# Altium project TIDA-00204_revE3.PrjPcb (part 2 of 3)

## Sheet TIDA-00204_revE3_PHY_2.SchDoc: =DocumentName
size 431 x 279 mm; Date: Not shown in title block; ApprovedBy: Not shown in title block; CheckedBy: Not shown in title block; Author: Not shown in title block; CompanyName: Not shown in title block; DrawnBy: K. Mogensen; Engineer: K. Mogensen; Organization: Not shown in title block; Address1: Not shown in title block; Address2: Not shown in title block; Address3: Not shown in title block; Address4: Not shown in title block; DocumentNumber: 4; Revision: Use project parameter SCH_Rev; SheetNumber: 4; SheetTotal: 10; PageSetup: Record=PageOptions¦CenterHorizontal=True¦CenterVertical=True¦PrintScale=0.62¦XCorrection=1.00¦YCorrection=1.00¦PrintKind=0¦BorderSize=5000000¦LeftOffset=0¦BottomOffset=0¦Orientation=2¦PaperLength=1000¦PaperWidth=1000¦Scale=100¦PaperSource=15¦PrintQuality=600¦MediaType=1¦DitherType=10¦PrintScaleMode=1¦PaperKind=Letter
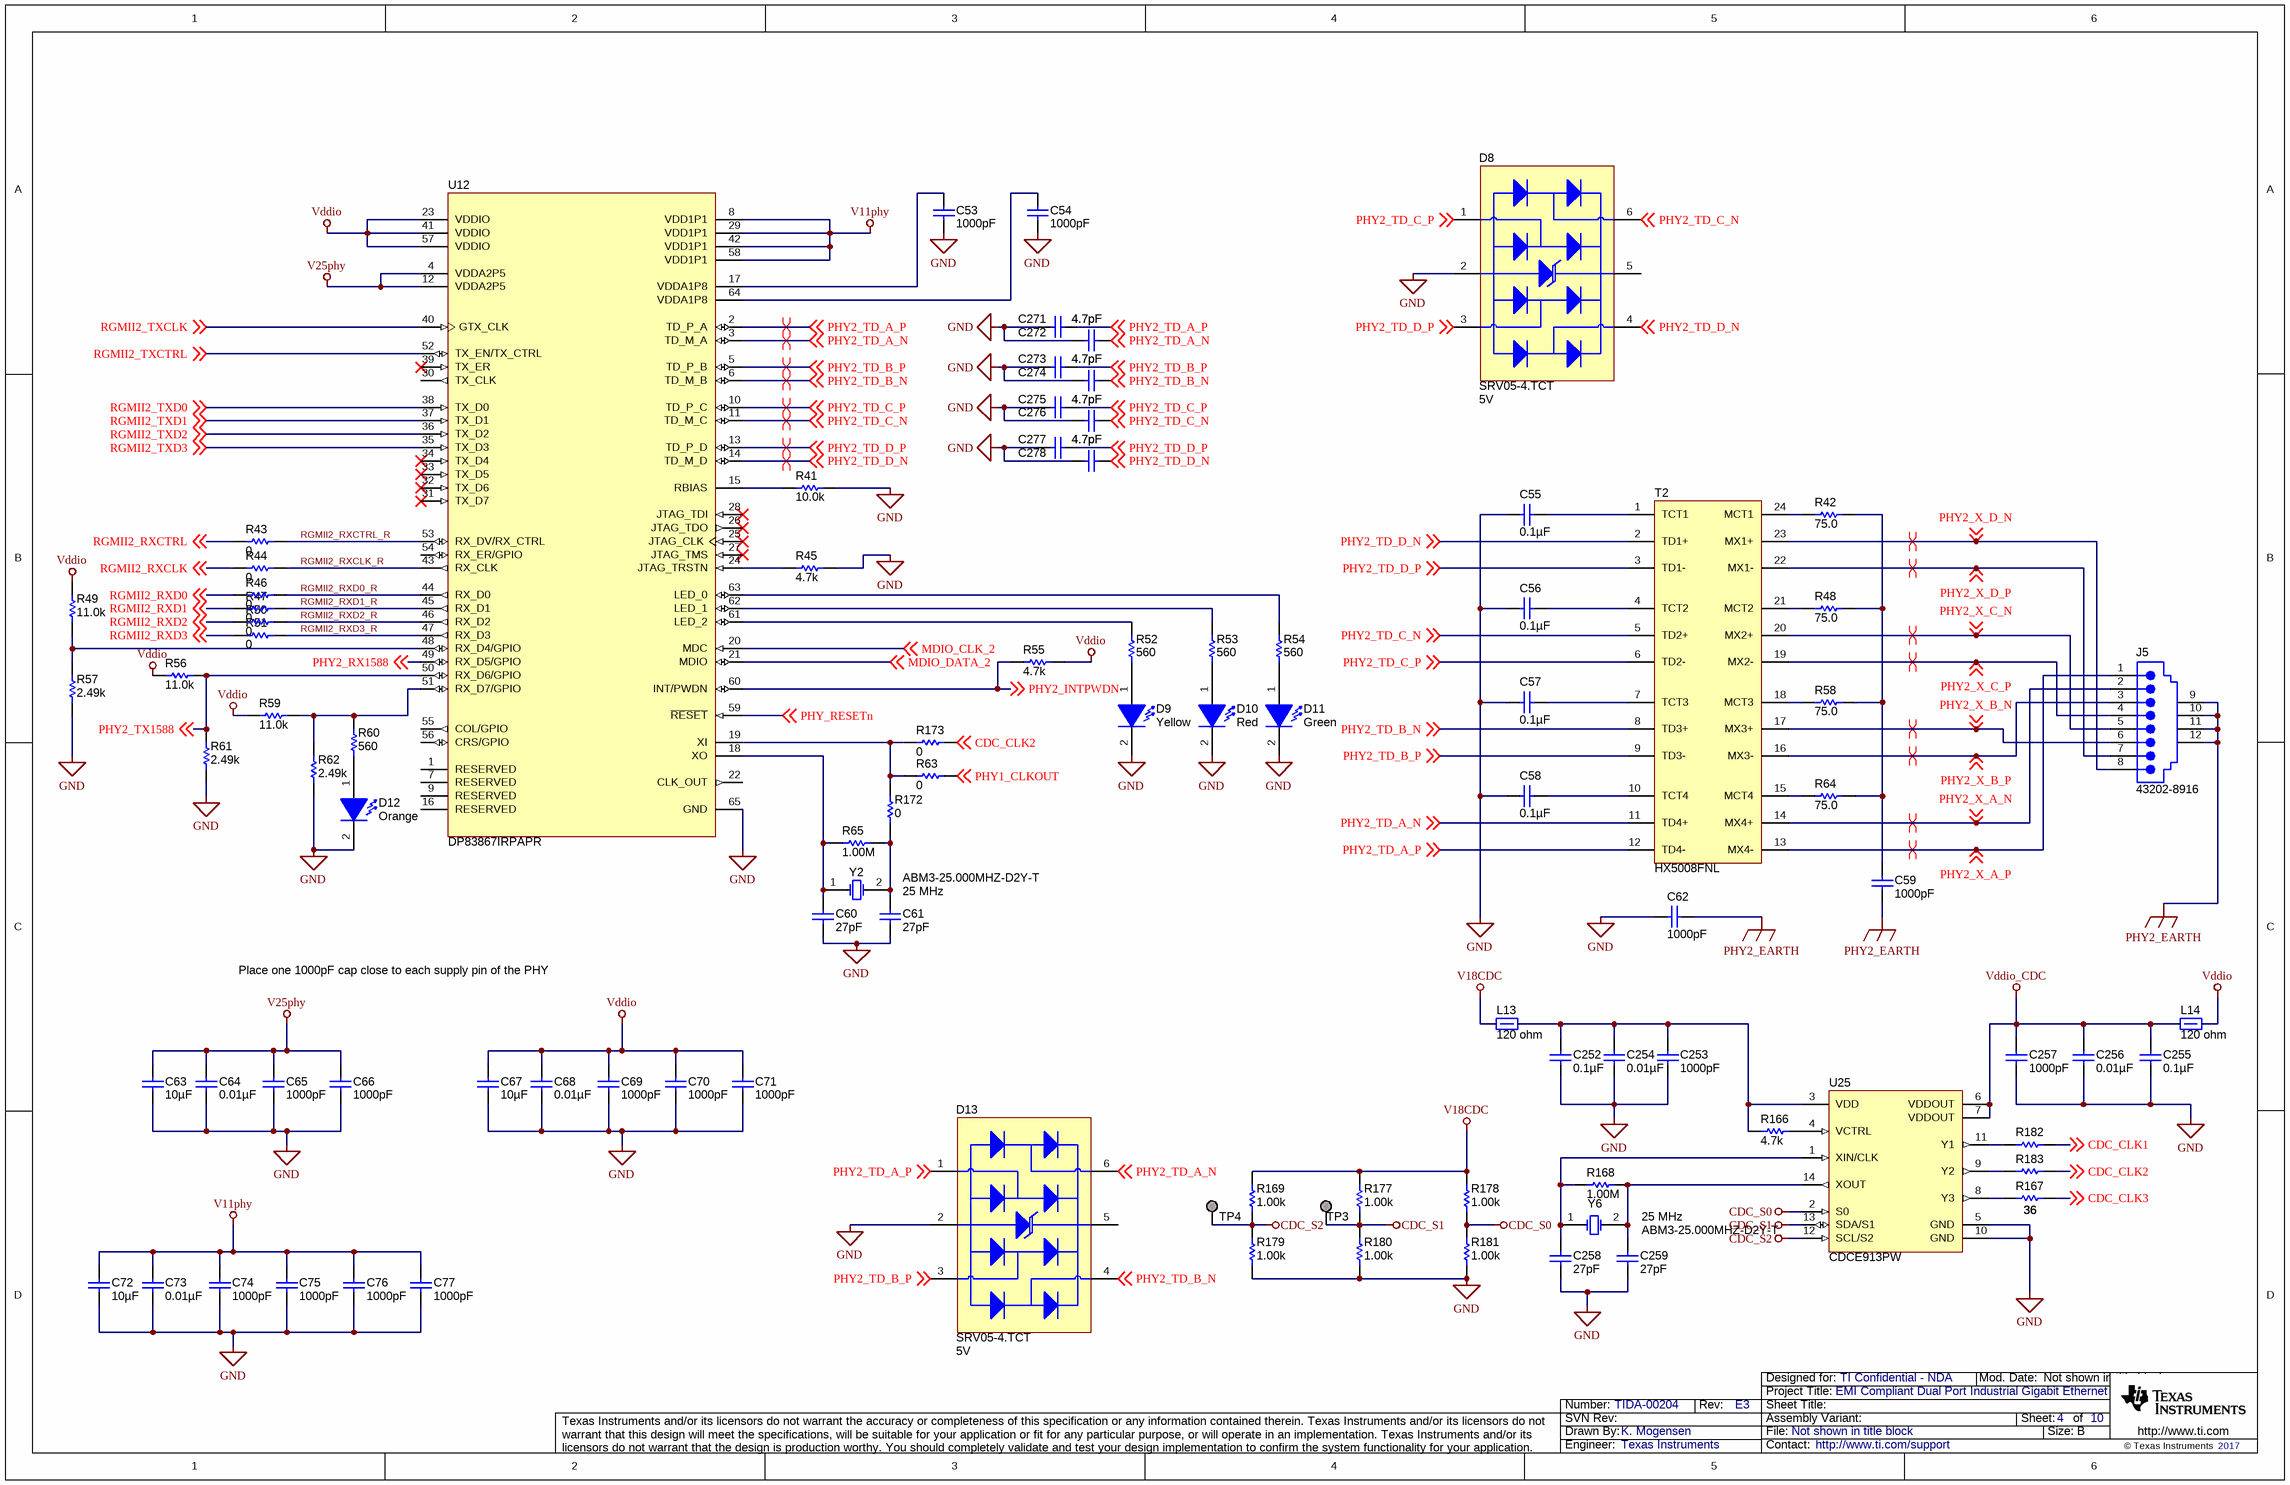
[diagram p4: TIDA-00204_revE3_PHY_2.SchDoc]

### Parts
C53  ValueDisplayed: 1000pF  [0201]  (hidden comment: GRM033R71C102KA01D)
C54  ValueDisplayed: 1000pF  [0201]  (hidden comment: GRM033R71C102KA01D)
C55  ValueDisplayed: 0.1µF  [0402]  (hidden comment: GRM155R71C104KA88D)
C56  ValueDisplayed: 0.1µF  [0402]  (hidden comment: GRM155R71C104KA88D)
C57  ValueDisplayed: 0.1µF  [0402]  (hidden comment: GRM155R71C104KA88D)
C58  ValueDisplayed: 0.1µF  [0402]  (hidden comment: GRM155R71C104KA88D)
C59  ValueDisplayed: 1000pF  [1206_190]  (hidden comment: 202R18W102KV4E)
C60  ValueDisplayed: 27pF  [0402]  (hidden comment: GRM1555C1H270JA01D)
C61  ValueDisplayed: 27pF  [0402]  (hidden comment: GRM1555C1H270JA01D)
C62  ValueDisplayed: 1000pF  [1812]  (hidden comment: 1812GC102KA1)
C63  ValueDisplayed: 10µF  [0603]  (hidden comment: C1608X5R1E106M080AC)
C64  ValueDisplayed: 0.01µF  [0201]  (hidden comment: GRM033R71A103KA01D)
C65  ValueDisplayed: 1000pF  [0201]  (hidden comment: GRM033R71C102KA01D)
C66  ValueDisplayed: 1000pF  [0201]  (hidden comment: GRM033R71C102KA01D)
C67  ValueDisplayed: 10µF  [0603]  (hidden comment: C1608X5R1E106M080AC)
C68  ValueDisplayed: 0.01µF  [0201]  (hidden comment: GRM033R71A103KA01D)
C69  ValueDisplayed: 1000pF  [0201]  (hidden comment: GRM033R71C102KA01D)
C70  ValueDisplayed: 1000pF  [0201]  (hidden comment: GRM033R71C102KA01D)
C71  ValueDisplayed: 1000pF  [0201]  (hidden comment: GRM033R71C102KA01D)
C72  ValueDisplayed: 10µF  [0603]  (hidden comment: C1608X5R1E106M080AC)
C73  ValueDisplayed: 0.01µF  [0201]  (hidden comment: GRM033R71A103KA01D)
C74  ValueDisplayed: 1000pF  [0201]  (hidden comment: GRM033R71C102KA01D)
C75  ValueDisplayed: 1000pF  [0201]  (hidden comment: GRM033R71C102KA01D)
C76  ValueDisplayed: 1000pF  [0201]  (hidden comment: GRM033R71C102KA01D)
C77  ValueDisplayed: 1000pF  [0201]  (hidden comment: GRM033R71C102KA01D)
C252  ValueDisplayed: 0.1µF  [0201]  (hidden comment: CL03A104KP3NNNC)
C253  ValueDisplayed: 1000pF  [0201]  (hidden comment: GRM033R71C102KA01D)
C254  ValueDisplayed: 0.01µF  [0201]  (hidden comment: GRM033R71A103KA01D)
C255  ValueDisplayed: 0.1µF  [0201]  (hidden comment: CL03A104KP3NNNC)
C256  ValueDisplayed: 0.01µF  [0201]  (hidden comment: GRM033R71A103KA01D)
C257  ValueDisplayed: 1000pF  [0201]  (hidden comment: GRM033R71C102KA01D)
C258  ValueDisplayed: 27pF  [0402]  (hidden comment: GRM1555C1H270JA01D)
C259  ValueDisplayed: 27pF  [0402]  (hidden comment: GRM1555C1H270JA01D)
C271  ValueDisplayed: 4.7pF  [0201]  (hidden comment: GRM0335C1H4R7CA01D)
C272  ValueDisplayed: 4.7pF  [0201]  (hidden comment: GRM0335C1H4R7CA01D)
C273  ValueDisplayed: 4.7pF  [0201]  (hidden comment: GRM0335C1H4R7CA01D)
C274  ValueDisplayed: 4.7pF  [0201]  (hidden comment: GRM0335C1H4R7CA01D)
C275  ValueDisplayed: 4.7pF  [0201]  (hidden comment: GRM0335C1H4R7CA01D)
C276  ValueDisplayed: 4.7pF  [0201]  (hidden comment: GRM0335C1H4R7CA01D)
C277  ValueDisplayed: 4.7pF  [0201]  (hidden comment: GRM0335C1H4R7CA01D)
C278  ValueDisplayed: 4.7pF  [0201]  (hidden comment: GRM0335C1H4R7CA01D)
D8  SRV05-4.TCT  value 5V  [SOT-23-6]
D9  value Yellow  [LY L29K_Yellow]  (hidden comment: LY L29K-J1K2-26-Z)
D10  value Red  [LS L29K_Red]  (hidden comment: LS L29K-G1J2-1-Z)
D11  value Green  [LG L29K_GREEN]  (hidden comment: LG L29K-G2J1-24-Z)
D12  value Orange  [LO L29K_Orange]  (hidden comment: LO L29K-J2L1-24-Z)
D13  SRV05-4.TCT  value 5V  [SOT-23-6]
J5  43202-8916  [Molex_43202-8916]
L13  value 120 ohm  [0402]  (hidden comment: MMZ1005Y121C)
L14  value 120 ohm  [0402]  (hidden comment: MMZ1005Y121C)
R41  ValueDisplayed: 10.0k  [0402]  (hidden comment: CRCW040210K0FKED)
R42  ValueDisplayed: 75.0  [0603]  (hidden comment: CRCW060375R0FKEA)
R43  ValueDisplayed: 0  [0402]  (hidden comment: CRCW04020000Z0ED)
R44  ValueDisplayed: 0  [0402]  (hidden comment: CRCW04020000Z0ED)
R45  ValueDisplayed: 4.7k  [0402]  (hidden comment: CRCW04024K70JNED)
R46  ValueDisplayed: 0  [0402]  (hidden comment: CRCW04020000Z0ED)
R47  ValueDisplayed: 0  [0402]  (hidden comment: CRCW04020000Z0ED)
R48  ValueDisplayed: 75.0  [0603]  (hidden comment: CRCW060375R0FKEA)
R49  ValueDisplayed: 11.0k  [0402]  (hidden comment: CRCW040211K0FKED)
R50  ValueDisplayed: 0  [0402]  (hidden comment: CRCW04020000Z0ED)
R51  ValueDisplayed: 0  [0402]  (hidden comment: CRCW04020000Z0ED)
R52  ValueDisplayed: 560  [0402]  (hidden comment: CRCW0402560RJNED)
R53  ValueDisplayed: 560  [0402]  (hidden comment: CRCW0402560RJNED)
R54  ValueDisplayed: 560  [0402]  (hidden comment: CRCW0402560RJNED)
R55  ValueDisplayed: 4.7k  [0402]  (hidden comment: CRCW04024K70JNED)
R56  ValueDisplayed: 11.0k  [0402]  (hidden comment: CRCW040211K0FKED)
R57  ValueDisplayed: 2.49k  [0402]  (hidden comment: CRCW04022K49FKED)
R58  ValueDisplayed: 75.0  [0603]  (hidden comment: CRCW060375R0FKEA)
R59  ValueDisplayed: 11.0k  [0402]  (hidden comment: CRCW040211K0FKED)
R60  ValueDisplayed: 560  [0402]  (hidden comment: CRCW0402560RJNED)
R61  ValueDisplayed: 2.49k  [0402]  (hidden comment: CRCW04022K49FKED)
R62  ValueDisplayed: 2.49k  [0402]  (hidden comment: CRCW04022K49FKED)
R63  ValueDisplayed: 0  [0402]  (hidden comment: CRCW04020000Z0ED)
R64  ValueDisplayed: 75.0  [0603]  (hidden comment: CRCW060375R0FKEA)
R65  ValueDisplayed: 1.00M  [0402]  (hidden comment: CRCW04021M00FKED)
R166  ValueDisplayed: 4.7k  [0402]  (hidden comment: CRCW04024K70JNED)
R167  ValueDisplayed: 36  [0402]  (hidden comment: CRCW040236R0JNED)
R168  ValueDisplayed: 1.00M  [0402]  (hidden comment: CRCW04021M00FKED)
R169  ValueDisplayed: 1.00k  [0402]  (hidden comment: CRCW04021K00FKED)
R172  ValueDisplayed: 0  [0402]  (hidden comment: CRCW04020000Z0ED)
R173  ValueDisplayed: 0  [0402]  (hidden comment: CRCW04020000Z0ED)
R177  ValueDisplayed: 1.00k  [0402]  (hidden comment: CRCW04021K00FKED)
R178  ValueDisplayed: 1.00k  [0402]  (hidden comment: CRCW04021K00FKED)
R179  ValueDisplayed: 1.00k  [0402]  (hidden comment: CRCW04021K00FKED)
R180  ValueDisplayed: 1.00k  [0402]  (hidden comment: CRCW04021K00FKED)
R181  ValueDisplayed: 1.00k  [0402]  (hidden comment: CRCW04021K00FKED)
R182  ValueDisplayed: 36  [0402]  (hidden comment: CRCW040236R0JNED)
R183  ValueDisplayed: 36  [0402]  (hidden comment: CRCW040236R0JNED)
T2  HX5008FNL  [PULSE_HX5008FNL]
TP3  TESTPOINT  [OXLEY_SMOX_060_B1_LP]  (value not drawn)  (no BOM)
TP4  TESTPOINT  [OXLEY_SMOX_060_B1_LP]  (value not drawn)  (no BOM)
U12  DP83867IRPAPR  [PAP0064M_N]
U25  CDCE913PW  [PW0014A_N]
Y2  ABM3-25.000MHZ-D2Y-T  Frequency: 25 MHz  [XTAL_ABM3]
Y6  ABM3-25.000MHZ-D2Y-T  Frequency: 25 MHz  [XTAL_ABM3]

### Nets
CDC_S0: R178.1 R181.2 U25.2(S0)
CDC_S1: R177.1 R180.2 TP3.1 U25.13(SDA/S1)
CDC_S2: R169.1 R179.2 TP4.1 U25.12(SCL/S2)
GND: C53.2 C54.2 C55.2 C56.2 C57.2 C58.2 C60.2 C61.2 C62.2 C63.2 C64.2 C65.2 C66.2 C67.2 C68.2 C69.2 C70.2 C71.2 C72.2 C73.2 C74.2 C75.2 C76.2 C77.2 C252.2 C253.2 C254.2 C255.2 C256.2 C257.2 C258.2 C259.2 C271.1 C272.1 C273.1 C274.1 C275.1 C276.1 C277.1 C278.1 D8.2 D9.2(K) D10.2(K) D11.2(K) D12.2(K) D13.2 R41.1 R45.1 R57.2 R61.1 R62.1 R179.1 R180.1 R181.1 U12.65(GND) U25.5(GND) U25.10(GND)
PHY2_EARTH: C59.2 C62.1 J5.9 J5.10 J5.11 J5.12
V11phy: C72.1 C73.1 C74.1 C75.1 C76.1 C77.1 U12.8(VDD1P1) U12.29(VDD1P1) U12.42(VDD1P1) U12.58(VDD1P1)
V18CDC: L13.1 R169.2 R177.2 R178.2
V25phy: C63.1 C64.1 C65.1 C66.1 U12.4(VDDA2P5) U12.12(VDDA2P5)
Vddio: C67.1 C68.1 C69.1 C70.1 C71.1 L14.1 R49.2 R55.1 R56.1 R59.2 U12.23(VDDIO) U12.41(VDDIO) U12.57(VDDIO)
Vddio_CDC: C255.1 C256.1 C257.1 L14.2 U25.6(VDDOUT) U25.7(VDDOUT)
CDC_CLK1: R182.2 ; off-sheet CDC_CLK1
CDC_CLK2: R173.2 R183.2 ; off-sheet CDC_CLK2
CDC_CLK3: R167.2 ; off-sheet CDC_CLK3
MDIO_CLK_2: U12.20(MDC) ; off-sheet MDIO_CLK_2
MDIO_DATA_2: U12.21(MDIO) ; off-sheet MDIO_DATA_2
PHY1_CLKOUT: R63.1 ; off-sheet PHY1_CLKOUT
PHY2_INTPWDN: R55.2 U12.60(INT/PWDN) ; off-sheet PHY2_INTPWDN
PHY2_RX1588: U12.49(RX_D5/GPIO) ; off-sheet PHY2_RX1588
PHY2_TD_A_N: C272.2 D13.6 T2.11(TD4+) U12.3(TD_M_A) ; off-sheet PHY2_TD_A_N
PHY2_TD_A_P: C271.2 D13.1 T2.12(TD4-) U12.2(TD_P_A) ; off-sheet PHY2_TD_A_P
PHY2_TD_B_N: C274.2 D13.4 T2.8(TD3+) U12.6(TD_M_B) ; off-sheet PHY2_TD_B_N
PHY2_TD_B_P: C273.2 D13.3 T2.9(TD3-) U12.5(TD_P_B) ; off-sheet PHY2_TD_B_P
PHY2_TD_C_N: C276.2 D8.6 T2.5(TD2+) U12.11(TD_M_C) ; off-sheet PHY2_TD_C_N
PHY2_TD_C_P: C275.2 D8.1 T2.6(TD2-) U12.10(TD_P_C) ; off-sheet PHY2_TD_C_P
PHY2_TD_D_N: C278.2 D8.4 T2.2(TD1+) U12.14(TD_M_D) ; off-sheet PHY2_TD_D_N
PHY2_TD_D_P: C277.2 D8.3 T2.3(TD1-) U12.13(TD_P_D) ; off-sheet PHY2_TD_D_P
PHY2_TX1588: R56.2 R61.2 U12.50(RX_D6/GPIO) ; off-sheet PHY2_TX1588
PHY2_X_A_N: J5.2 T2.14(MX4+) ; off-sheet PHY2_X_A_N
PHY2_X_A_P: J5.1 T2.13(MX4-) ; off-sheet PHY2_X_A_P
PHY2_X_B_N: J5.6 T2.17(MX3+) ; off-sheet PHY2_X_B_N
PHY2_X_B_P: J5.3 T2.16(MX3-) ; off-sheet PHY2_X_B_P
PHY2_X_C_N: J5.5 T2.20(MX2+) ; off-sheet PHY2_X_C_N
PHY2_X_C_P: J5.4 T2.19(MX2-) ; off-sheet PHY2_X_C_P
PHY2_X_D_N: J5.8 T2.23(MX1+) ; off-sheet PHY2_X_D_N
PHY2_X_D_P: J5.7 T2.22(MX1-) ; off-sheet PHY2_X_D_P
PHY_RESETn: U12.59(~{RESET}) ; off-sheet PHY_RESETn
RGMII2_RXCLK: R44.1 ; off-sheet RGMII2_RXCLK
RGMII2_RXCLK_R: R44.2 U12.43(RX_CLK)
RGMII2_RXCTRL: R43.1 ; off-sheet RGMII2_RXCTRL
RGMII2_RXCTRL_R: R43.2 U12.53(RX_DV/RX_CTRL)
RGMII2_RXD0: R46.1 ; off-sheet RGMII2_RXD0
RGMII2_RXD0_R: R46.2 U12.44(RX_D0)
RGMII2_RXD1: R47.1 ; off-sheet RGMII2_RXD1
RGMII2_RXD1_R: R47.2 U12.45(RX_D1)
RGMII2_RXD2: R50.1 ; off-sheet RGMII2_RXD2
RGMII2_RXD2_R: R50.2 U12.46(RX_D2)
RGMII2_RXD3: R51.1 ; off-sheet RGMII2_RXD3
RGMII2_RXD3_R: R51.2 U12.47(RX_D3)
RGMII2_TXCLK: U12.40(GTX_CLK) ; off-sheet RGMII2_TXCLK
RGMII2_TXCTRL: U12.52(TX_EN/TX_CTRL) ; off-sheet RGMII2_TXCTRL
RGMII2_TXD0: U12.38(TX_D0) ; off-sheet RGMII2_TXD0
RGMII2_TXD1: U12.37(TX_D1) ; off-sheet RGMII2_TXD1
RGMII2_TXD2: U12.36(TX_D2) ; off-sheet RGMII2_TXD2
RGMII2_TXD3: U12.35(TX_D3) ; off-sheet RGMII2_TXD3
NetC53_1: C53.1 U12.17(VDDA1P8)
NetC54_1: C54.1 U12.64(VDDA1P8)
NetC55_1: C55.1 T2.1(TCT1)
NetC56_1: C56.1 T2.4(TCT2)
NetC57_1: C57.1 T2.7(TCT3)
NetC58_1: C58.1 T2.10(TCT4)
NetC59_1: C59.1 R42.2 R48.2 R58.2 R64.2
NetC60_1: C60.1 R65.1 U12.18(XO) Y2.1(OSC1)
NetC61_1: C61.1 R65.2 R172.1 Y2.2(OSC2)
NetC252_1: C252.1 C253.1 C254.1 L13.2 R166.1 U25.3(VDD)
NetC258_1: C258.1 R168.1 U25.1(XIN/CLK) Y6.1(OSC1)
NetC259_1: C259.1 R168.2 U25.14(XOUT) Y6.2(OSC2)
NetD9_1: D9.1(A) R52.1
NetD10_1: D10.1(A) R53.1
NetD11_1: D11.1(A) R54.1
NetD12_1: D12.1(A) R60.2
NetR41_2: R41.2 U12.15(RBIAS)
NetR42_1: R42.1 T2.24(MCT1)
NetR45_2: R45.2 U12.24(JTAG_TRSTN)
NetR48_1: R48.1 T2.21(MCT2)
NetR49_1: R49.1 R57.1 U12.48(RX_D4/GPIO)
NetR52_2: R52.2 U12.61(LED_2)
NetR53_2: R53.2 U12.62(LED_1)
NetR54_2: R54.2 U12.63(LED_0)
NetR58_1: R58.1 T2.18(MCT3)
NetR59_1: R59.1 R60.1 R62.2 U12.51(RX_D7/GPIO)
NetR63_2: R63.2 R172.2 R173.1 U12.19(XI)
NetR64_1: R64.1 T2.15(MCT4)
NetR166_2: R166.2 U25.4(VCTRL)
NetR167_1: R167.1 U25.8(Y3)
NetR182_1: R182.1 U25.11(Y1)
NetR183_1: R183.1 U25.9(Y2)

Not connected (* = marked no-connect by the designer): D8 5; D13 5; U12 1(RESERVED) 7(RESERVED) 9(RESERVED) 16(RESERVED) 22(CLK_OUT) 25(JTAG_CLK)* 26(JTAG_TDO)* 27(JTAG_TMS)* 28(JTAG_TDI)* 30(TX_CLK) 31(TX_D7)* 32(TX_D6)* 33(TX_D5)* 34(TX_D4)* 39(TX_ER)* 54(RX_ER/GPIO) 55(COL/GPIO) 56(CRS/GPIO)

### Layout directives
differential pair: PHY2_TD_A_N, PHY2_TD_A_P, PHY2_TD_B_N, PHY2_TD_B_P, PHY2_TD_C_N, PHY2_TD_C_P, PHY2_TD_D_N, PHY2_TD_D_P, PHY2_X_A_N, PHY2_X_A_P, PHY2_X_B_N, PHY2_X_B_P, PHY2_X_C_N, PHY2_X_C_P, PHY2_X_D_N, PHY2_X_D_P

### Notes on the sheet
- Place one 1000pF cap close to each supply pin of the PHY

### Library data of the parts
C53 C54 C65 C66 C69-C71 C74-C77 C253 C257 = GRM033R71C102KA01D: CAP, CERM, 1000 pF, 16 V, +/- 10%, X7R, 0201; Manufacturer: MuRata; Polarized: N; CompType: Capacitor; Value: 1000pF; U/M: EA; Cap_F: 0.000000001; Tolerance_%: 10; Value1: Unknown; VDC_V: 16; Value2: 16V; TaMin_C: -55; TaMax_C: 125
C55-C58 = GRM155R71C104KA88D: CAP, CERM, 0.1 µF, 16 V, +/- 10%, X7R, 0402; Manufacturer: MuRata; Polarized: N; CompType: Capacitor; Value: 0.1uF; U/M: EA; Cap_F: 0.0000001; Tolerance_%: 10; Value1: Unknown; VDC_V: 16; Value2: 16V; TaMin_C: -55; TaMax_C: 125
C59 = 202R18W102KV4E: CAP, CERM, 1000 pF, 2000 V, +/- 10%, X7R, 1206_190; Manufacturer: Johanson Technology; Polarized: N; CompType: Capacitor; Value: 1000pF; U/M: EA; Cap_F: 0.000000001; Tolerance_%: 10; Value1: Unknown; VDC_V: 2000; Value2: 2000V; TaMin_C: -55; TaMax_C: 125
C60 C61 C258 C259 = GRM1555C1H270JA01D: CAP, CERM, 27 pF, 50 V, +/- 5%, C0G/NP0, 0402; Manufacturer: MuRata; Polarized: N; CompType: Capacitor; Value: 27pF; U/M: EA; Cap_F: 0.000000000027; Tolerance_%: 5; Value1: Unknown; VDC_V: 50; Value2: 50V; TaMin_C: -55; TaMax_C: 125
C62 = 1812GC102KA1: CAP, CERM, 1000 pF, 2000 V, +/- 10%, X7R, 1812; Manufacturer: AVX; Polarized: N; CompType: Capacitor; Value: 1000pF; U/M: EA; Cap_F: 0.000000001; Tolerance_%: 10; Value1: Unknown; VDC_V: 2000; Value2: 2000V; TaMin_C: -55; TaMax_C: 125
C63 C67 C72 = C1608X5R1E106M080AC: CAP, CERM, 10 µF, 25 V, +/- 20%, X5R, 0603; Manufacturer: TDK; Polarized: N; CompType: Capacitor; Value: 10uF; U/M: EA; Cap_F: 0.00001; Tolerance_%: 20; Value1: Unknown; VDC_V: 25; Value2: 25V; TaMin_C: -55; TaMax_C: 85
C64 C68 C73 C254 C256 = GRM033R71A103KA01D: CAP, CERM, 0.01 µF, 10 V, +/- 10%, X7R, 0201; Manufacturer: MuRata; Polarized: N; CompType: Capacitor; Value: 0.01uF; U/M: EA; Cap_F: 0.00000001; Tolerance_%: 10; Value1: Unknown; Value2: 10V; TaMin_C: -55; TaMax_C: 125
C252 C255 = CL03A104KP3NNNC: CAP, CERM, 0.1 µF, 10 V, +/- 10%, X5R, 0201; Manufacturer: Samsung; Polarized: N; CompType: Capacitor; Value: 0.1uF; U/M: EA; Cap_F: 0.0000001; Tolerance_%: 10; Value1: Unknown; Value2: 10V; TaMin_C: -55; TaMax_C: 85
C271-C278 = GRM0335C1H4R7CA01D: CAP, CERM, 4.7 pF, 50 V, +/- 5%, C0G/NP0, 0201; Manufacturer: MuRata; Polarized: N; CompType: Capacitor; Value: 4.7pF; U/M: EA; Cap_F: 0.0000000000047; Tolerance_%: 5; Value1: Unknown; VDC_V: 50; Value2: 50V; TaMin_C: -55; TaMax_C: 125
D8 D13 = SRV05-4.TCT: Diode, TVS, Bi, 5 V, 300 W, SOT-23-6; Manufacturer: Semtech; SymbolCreator: Altium; U/M: EA; Power_W: 300; Vr_V: 5; Value1: 300W
D9 = LY L29K-J1K2-26-Z: LED, Yellow, SMD; Manufacturer: OSRAM; Vf_V: 1.8; Value2: 1.8V; Io_A: 0.002; Tjmax_C: 110; Value1: W; U/M: EA
D10 = LS L29K-G1J2-1-Z: LED, Red, SMD; Manufacturer: OSRAM; Vf_V: 1.8; Value2: 1.8V; Io_A: 0.02; Vr_V: 12; Tjmax_C: 110; Value1: W; Angle: 160; U/M: EA
D11 = LG L29K-G2J1-24-Z: LED, Green, SMD; Manufacturer: OSRAM; Vf_V: 1.7; Value2: 1.7V; Io_A: 0.002; Tjmax_C: 110; Value1: W; U/M: EA
D12 = LO L29K-J2L1-24-Z: LED, Orange, SMD; Manufacturer: OSRAM; Vf_V: 1.8; Value2: 1.8V; Io_A: 0.02; Vr_V: 12; Tjmax_C: 110; Value1: W; Angle: 160; U/M: EA
J5 = 43202-8916: Modular Jack(Shielded), Gold, R/A, TH; Manufacturer: Molex; SymbolCreator: Altium; U/M: EA
L13 L14 = MMZ1005Y121C: Ferrite Bead, 120 ohm @ 100 MHz, 0.4 A, 0402; Manufacturer: TDK; Imax_A: 0.4; DCR_ohm: 0.18; Value1: 0.18 ohm; Value2: 0.4A; ZTyp@100MHz_Ohm: 120
R41 = CRCW040210K0FKED: RES, 10.0 k, 1%, 0.063 W, 0402; Manufacturer: Vishay-Dale; CompType: Resistor; Value: 10.0k; Res_ohm: 10000; Value_Code: 10k0; Tolerance_%: 1; Power_W: 0.063; Value2: 0.063W; VDC_V: 50; TempCo: 100 ppm/C; EIA_Code: E96; U/M: EA
R42 R48 R58 R64 = CRCW060375R0FKEA: RES, 75.0, 1%, 0.1 W, 0603; Manufacturer: Vishay-Dale; CompType: Resistor; Value: 75.0; Res_ohm: 75; Value_Code: 75R0; Tolerance_%: 1; Power_W: 0.1; Value2: 0.1W; TempCo: 100 ppm/C; EIA_Code: E96; U/M: EA
R43 R44 R46 R47 R50 R51 R63 R172 R173 = CRCW04020000Z0ED: RES, 0, 5%, 0.063 W, 0402; Manufacturer: Vishay-Dale; CompType: Resistor; Value: 0; Value_Code: 0000; Tolerance_%: 5; Power_W: 0.063; Value2: 0.063W; VDC_V: 50; TempCo: 200 ppm/C; EIA_Code: E24; U/M: EA
R45 R55 R166 = CRCW04024K70JNED: RES, 4.7 k, 5%, 0.063 W, 0402; Manufacturer: Vishay-Dale; CompType: Resistor; Value: 4.7k; Res_ohm: 4700; Value_Code: 4k70; Tolerance_%: 5; Power_W: 0.063; Value2: 0.063W; VDC_V: 50; TempCo: 200 ppm/C; EIA_Code: E24; U/M: EA
R49 R56 R59 = CRCW040211K0FKED: RES, 11.0 k, 1%, 0.063 W, 0402; Manufacturer: Vishay-Dale; CompType: Resistor; Value: 11.0k; Res_ohm: 11000; Value_Code: 11k0; Tolerance_%: 1; Power_W: 0.063; Value2: 0.063W; VDC_V: 50; TempCo: 100 ppm/C; EIA_Code: E96; U/M: EA
R52-R54 R60 = CRCW0402560RJNED: RES, 560, 5%, 0.063 W, 0402; Manufacturer: Vishay-Dale; CompType: Resistor; Value: 560; Value_Code: 560R; Tolerance_%: 5; Power_W: 0.063; Value2: 0.063W; VDC_V: 50; TempCo: 200 ppm/C; EIA_Code: E24; U/M: EA
R57 R61 R62 = CRCW04022K49FKED: RES, 2.49 k, 1%, 0.063 W, 0402; Manufacturer: Vishay-Dale; CompType: Resistor; Value: 2.49k; Res_ohm: 2490; Value_Code: 2k49; Tolerance_%: 1; Power_W: 0.063; Value2: 0.063W; VDC_V: 50; TempCo: 100 ppm/C; EIA_Code: E96; U/M: EA
R65 R168 = CRCW04021M00FKED: RES, 1.00 M, 1%, 0.063 W, 0402; Manufacturer: Vishay-Dale; CompType: Resistor; Value: 1.00Meg; Res_ohm: 1000000; Value_Code: 1M00; Tolerance_%: 1; Power_W: 0.063; Value2: 0.063W; VDC_V: 50; TempCo: 100 ppm/C; EIA_Code: E96; U/M: EA
R167 R182 R183 = CRCW040236R0JNED: RES, 36, 5%, 0.063 W, 0402; Manufacturer: Vishay-Dale; CompType: Resistor; Value: 36; Value_Code: 36R0; Tolerance_%: 5; Power_W: 0.063; Value2: 0.063W; VDC_V: 50; TempCo: 200 ppm/C; EIA_Code: E24; U/M: EA
R169 R177-R181 = CRCW04021K00FKED: RES, 1.00 k, 1%, 0.063 W, 0402; Manufacturer: Vishay-Dale; CompType: Resistor; Value: 1.00k; Res_ohm: 1000; Value_Code: 1k00; Tolerance_%: 1; Power_W: 0.063; Value2: 0.063W; VDC_V: 50; TempCo: 100 ppm/C; EIA_Code: E96; U/M: EA
T2 = HX5008FNL: Transformer, 325 uH, SMT; Manufacturer: Pulse Engineering; SymbolCreator: Altium; Value: 325 uH; U/M: EA
TP3 TP4 = SMOX/060/B1LP.R3K: Test Point, Silver, SMD; Manufacturer: Oxley; U/M: EA
U12 = DP83867IRPAPR: Robust, Low Power 10/100/1000 Ethernet Physical Layer Transceiver, PAP0064M; Alternate PartNumber: DP83867IRPAPT; Manufacturer: Texas Instruments; SymbolCreator: Altium; CompType: IC; U/M: EA
U25 = CDCE913PW: Programmable 1-PLL VCXO Clock Synthesizer With 1.8-V, 2.5-V, and 3.3-V Outputs, PW0014A; Manufacturer: Texas Instruments; SymbolCreator: a0411947; CompType: IC; U/M: EA
Y2 Y6 = ABM3-25.000MHZ-D2Y-T: Crystal, 25 MHz, 18 pF, SMD; Manufacturer: Abracon Corportation; SymbolCreator: a0412235; U/M: EA; TaMin_C: -40; TaMax_C: 85; Frequency Stability: ±30ppm

## Sheet TIDA-00204_revE3_PS_0.SchDoc: =DocumentName
size 431 x 279 mm; Date: Not shown in title block; ApprovedBy: Not shown in title block; CheckedBy: Not shown in title block; Author: Not shown in title block; CompanyName: Not shown in title block; DrawnBy: K. Mogensen; Engineer: K. Mogensen; Organization: Not shown in title block; Address1: Not shown in title block; Address2: Not shown in title block; Address3: Not shown in title block; Address4: Not shown in title block; DocumentNumber: 1; Revision: Use project parameter SCH_Rev; SheetNumber: 1; SheetTotal: 10; PageSetup: Record=PageOptions¦CenterHorizontal=True¦CenterVertical=True¦PrintScale=0.62¦XCorrection=1.00¦YCorrection=1.00¦PrintKind=0¦BorderSize=5000000¦LeftOffset=0¦BottomOffset=0¦Orientation=2¦PaperLength=1000¦PaperWidth=1000¦Scale=100¦PaperSource=15¦PrintQuality=600¦MediaType=1¦DitherType=10¦PaperKind=Letter¦PrintScaleMode=1
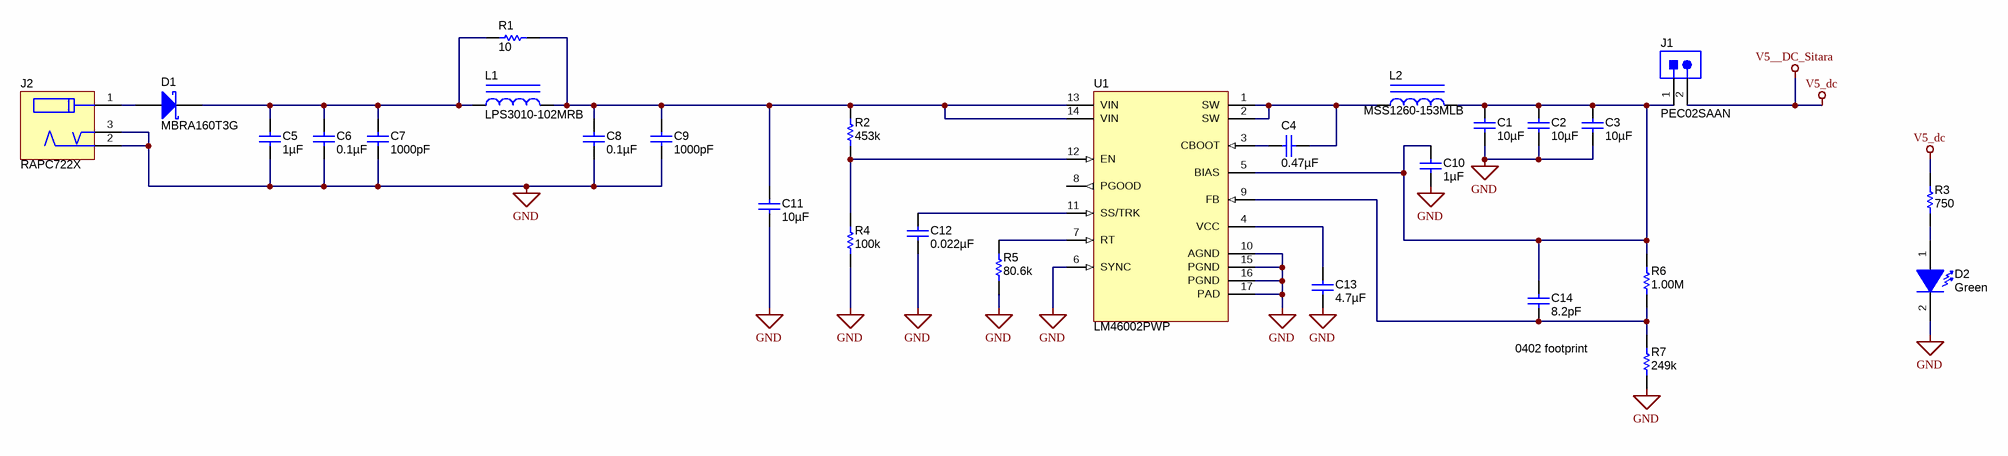
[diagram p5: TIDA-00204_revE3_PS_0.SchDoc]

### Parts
C1  ValueDisplayed: 10µF  [0603]  (hidden comment: C1608X5R1E106M080AC)
C2  ValueDisplayed: 10µF  [0603]  (hidden comment: C1608X5R1E106M080AC)
C3  ValueDisplayed: 10µF  [0603]  (hidden comment: C1608X5R1E106M080AC)
C4  ValueDisplayed: 0.47µF  [0805_HV]  (hidden comment: GRM21BR72A474KA73L)
C5  ValueDisplayed: 1µF  [0805_145]  (hidden comment: C2012X7S2A105K125AB)
C6  ValueDisplayed: 0.1µF  [0603]  (hidden comment: GRM188R72A104KA35D)
C7  ValueDisplayed: 1000pF  [0603]  (hidden comment: GRM188R72A102KA01D)
C8  ValueDisplayed: 0.1µF  [0603]  (hidden comment: GRM188R72A104KA35D)
C9  ValueDisplayed: 1000pF  [0603]  (hidden comment: GRM188R72A102KA01D)
C10  ValueDisplayed: 1µF  [0603]  (hidden comment: GRM188R71E105KA12D)
C11  ValueDisplayed: 10µF  [2220]  (hidden comment: C5750X7S2A106M)
C12  ValueDisplayed: 0.022µF  [0402]  (hidden comment: GRM155R71H223KA12D)
C13  ValueDisplayed: 4.7µF  [0603]  (hidden comment: GRM188R61C475KAAJ)
C14  ValueDisplayed: 8.2pF  [0402]  (hidden comment: GRM1555C1E8R2CA01D)
D1  MBRA160T3G  [SMA]
D2  value Green  [LG L29K_GREEN]  (hidden comment: LG L29K-G2J1-24-Z)
J1  PEC02SAAN  [CONN_PEC02SAAN]
J2  RAPC722X  [CONN_RAPC722X]
L1  LPS3010-102MRB  [LPS3010]
L2  MSS1260-153MLB  [MSS1260]
R1  value 10  [0603]  (hidden comment: CRCW060310R0JNEAHP)
R2  ValueDisplayed: 453k  [0402]  (hidden comment: CRCW0402453KFKED)
R3  ValueDisplayed: 750  [0402]  (hidden comment: CRCW0402750RJNED)
R4  ValueDisplayed: 100k  [0402]  (hidden comment: CRCW0402100KFKED)
R5  ValueDisplayed: 80.6k  [0402]  (hidden comment: CRCW040280K6FKED)
R6  ValueDisplayed: 1.00M  [0402]  (hidden comment: CRCW04021M00FKED)
R7  ValueDisplayed: 249k  [0402]  (hidden comment: CRCW0402249KFKED)
U1  LM46002PWP  [PWP0016A_N]

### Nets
GND: C1.2 C2.2 C3.2 C5.2 C6.2 C7.2 C8.2 C9.2 C10.2 C11.2 C12.2 C13.2 D2.2(K) J2.2 J2.3 R4.1 R5.1 R7.1 U1.6(SYNC) U1.10(AGND) U1.15(PGND) U1.16(PGND) U1.17(PAD)
V5__DC_Sitara: J1.2 R3.2  [also labelled V5_dc]
NetC1_1: C1.1 C2.1 C3.1 C10.1 C14.1 J1.1 L2.2 R6.2 U1.5(BIAS)
NetC4_1: C4.1 L2.1 U1.1(SW) U1.2(SW)
NetC4_2: C4.2 U1.3(CBOOT)
NetC5_1: C5.1 C6.1 C7.1 D1.1(K) L1.1 R1.1
NetC8_1: C8.1 C9.1 C11.1 L1.2 R1.2 R2.2 U1.13(VIN) U1.14(VIN)
NetC12_1: C12.1 U1.11(SS/TRK)
NetC13_1: C13.1 U1.4(VCC)
NetC14_2: C14.2 R6.1 R7.2 U1.9(FB)
NetD1_2: D1.2(A) J2.1
NetD2_1: D2.1(A) R3.1
NetR2_1: R2.1 R4.2 U1.12(EN)
NetR5_2: R5.2 U1.7(RT)

Not connected (* = marked no-connect by the designer): U1 8(PGOOD)

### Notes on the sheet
- 0402 footprint

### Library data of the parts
C1-C3 = C1608X5R1E106M080AC: as C63 on sheet TIDA-00204_revE3_PHY_2
C4 = GRM21BR72A474KA73L: CAP, CERM, 0.47 µF, 100 V, +/- 10%, X7R, 0805; Manufacturer: MuRata; Polarized: N; CompType: Capacitor; Value: 0.47uF; U/M: EA; Cap_F: 0.00000047; Tolerance_%: 10; Value1: Unknown; VDC_V: 100; Value2: 100V; TaMin_C: -55; TaMax_C: 125; Cap_Case: 0805
C5 = C2012X7S2A105K125AB: CAP, CERM, 1 µF, 100 V, +/- 10%, X7S, 0805; Manufacturer: TDK; Polarized: N; CompType: Capacitor; Value: 1uF; U/M: EA; Cap_F: 0.000001; Tolerance_%: 10; Value1: Unknown; VDC_V: 100; Value2: 100V; TaMin_C: -55; TaMax_C: 125
C6 C8 = GRM188R72A104KA35D: CAP, CERM, 0.1 µF, 100 V, +/- 10%, X7R, 0603; Manufacturer: MuRata; Polarized: N; CompType: Capacitor; Value: 0.1uF; U/M: EA; Cap_F: 0.0000001; Tolerance_%: 10; Value1: Unknown; VDC_V: 100; Value2: 100V; TaMin_C: -55; TaMax_C: 125
C7 C9 = GRM188R72A102KA01D: CAP, CERM, 1000 pF, 100 V, +/- 10%, X7R, 0603; Manufacturer: MuRata; Polarized: N; CompType: Capacitor; Value: 1000pF; U/M: EA; Cap_F: 0.000000001; Tolerance_%: 10; Value1: Unknown; VDC_V: 100; Value2: 100V; TaMin_C: -55; TaMax_C: 125
C10 = GRM188R71E105KA12D: CAP, CERM, 1 µF, 25 V, +/- 10%, X7R, 0603; Manufacturer: MuRata; Polarized: N; CompType: Capacitor; Value: 1uF; U/M: EA; Cap_F: 0.000001; Tolerance_%: 10; Value1: Unknown; VDC_V: 25; Value2: 25V; TaMin_C: -55; TaMax_C: 125
C11 = C5750X7S2A106M: CAP, CERM, 10 µF, 100 V, +/- 20%, X7S, 2220; Manufacturer: TDK; Polarized: N; CompType: Capacitor; Value: 10uF; U/M: EA; Cap_F: 0.00001; Tolerance_%: 20; ESR_ohm: 0.005; Value1: 0.005 ohm; VDC_V: 100; Value2: 100V; IRMS_A: 6.45; TaMin_C: -55; TaMax_C: 125
C12 = GRM155R71H223KA12D: CAP, CERM, 0.022 µF, 50 V, +/- 10%, X7R, 0402; Manufacturer: MuRata; Polarized: N; CompType: Capacitor; Value: 0.022uF; U/M: EA; Cap_F: 0.000000022; Tolerance_%: 10; Value1: Unknown; VDC_V: 50; Value2: 50V; TaMin_C: -55; TaMax_C: 125
C13 = GRM188R61C475KAAJ: CAP, CERM, 4.7 µF, 16 V, +/- 10%, X5R, 0603; Manufacturer: MuRata; Polarized: N; CompType: Capacitor; Value: 4.7uF; U/M: EA; Cap_F: 0.0000047; Tolerance_%: 10; Value1: Unknown; VDC_V: 16; Value2: 16V; TaMin_C: -55; TaMax_C: 85
C14 = GRM1555C1E8R2CA01D: CAP, CERM, 8.2 pF, 25 V, +/- 5%, C0G/NP0, 0402; Manufacturer: MuRata; Polarized: N; CompType: Capacitor; Value: 8.2pF; U/M: EA; Cap_F: 0.0000000000082; Tolerance_%: 5; Value1: Unknown; VDC_V: 25; Value2: 25V; TaMin_C: -55; TaMax_C: 125
D1 = MBRA160T3G: Diode, Schottky, 60V, 1A, SMA; Manufacturer: ON Semiconductor; U/M: EA; Vf_V: 0.51; Value2: 0.51V; Io_A: 1; Vr_V: 60; TJmax_C: 150; RJC_CperW: 35
D2 = LG L29K-G2J1-24-Z: as D11 on sheet TIDA-00204_revE3_PHY_2
J1 = PEC02SAAN: Header, 100mil, 2x1, Tin, TH; Manufacturer: Sullins Connector Solutions; SymbolCreator: a0412235; U/M: EA
J2 = RAPC722X: Power Jack, mini, 2.1mm OD, R/A, TH; Manufacturer: Switchcraft; SymbolCreator: a0799628; U/M: EA
L1 = LPS3010-102MRB: Inductor, Shielded Drum Core, Ferrite, 1 µH, 1.5 A, 0.085 ohm, SMD; Manufacturer: Coilcraft; Value: 1uH; Ind_H: 1.0E-6; ValueDisplayed: 1µH; Imax_A: 1.5; Irms: 1.5A @ 40C rise; Isat: 1.6A @ 30% inductance drop; DCR_ohm: 0.085; Value2: 1.5A
L2 = MSS1260-153MLB: Inductor, Shielded Drum Core, Ferrite, 15 µH, 3.5 A, 0.03 ohm, SMD; Manufacturer: Coilcraft; Value: 15uH; Ind_H: 15.0E-6; ValueDisplayed: 15µH; Imax_A: 3.5; Irms: 3.5A @ 40C rise; Isat: 5.78A @ 30% inductance drop; DCR_ohm: 0.03; Value2: 3.5A
R1 = CRCW060310R0JNEAHP: RES, 10 ohm, 5%, 0.25W, 0603; Manufacturer: Vishay-Dale; CompType: Resistor; Value_Code: 10R0; Tolerance_%: 5; Power_W: 0.25; VDC_V: 75; TempCo: 200 ppm/C; EIA_Code: E24; U/M: EA
R2 = CRCW0402453KFKED: RES, 453 k, 1%, 0.063 W, 0402; Manufacturer: Vishay-Dale; CompType: Resistor; Value: 453k; Res_ohm: 453000; Tolerance_%: 1; Power_W: 0.063; Value2: 0.063W; VDC_V: 50; TempCo: 100 ppm/C; EIA_Code: E96; U/M: EA
R3 = CRCW0402750RJNED: RES, 750, 5%, 0.063 W, 0402; Manufacturer: Vishay-Dale; CompType: Resistor; Value: 750; Value_Code: 750R; Tolerance_%: 5; Power_W: 0.063; Value2: 0.063W; VDC_V: 50; TempCo: 200 ppm/C; EIA_Code: E24; U/M: EA
R4 = CRCW0402100KFKED: RES, 100 k, 1%, 0.063 W, 0402; Manufacturer: Vishay-Dale; CompType: Resistor; Value: 100k; Res_ohm: 100000; Tolerance_%: 1; Power_W: 0.063; Value2: 0.063W; VDC_V: 50; TempCo: 100 ppm/C; EIA_Code: E96; U/M: EA
R5 = CRCW040280K6FKED: RES, 80.6 k, 1%, 0.063 W, 0402; Manufacturer: Vishay-Dale; CompType: Resistor; Value: 80.6k; Res_ohm: 80600; Value_Code: 80k6; Tolerance_%: 1; Power_W: 0.063; Value2: 0.063W; VDC_V: 50; TempCo: 100 ppm/C; EIA_Code: E96; U/M: EA
R6 = CRCW04021M00FKED: as R65 on sheet TIDA-00204_revE3_PHY_2
R7 = CRCW0402249KFKED: RES, 249 k, 1%, 0.063 W, 0402; Manufacturer: Vishay-Dale; CompType: Resistor; Value: 249k; Res_ohm: 249000; Tolerance_%: 1; Power_W: 0.063; Value2: 0.063W; VDC_V: 50; TempCo: 100 ppm/C; EIA_Code: E96; U/M: EA
U1 = LM46002PWP: 3.5V to 60V 2A Synchronous Step-Down Voltage Regulator, PWP0016A; Alternate Manufacturer: None; Manufacturer: Texas Instruments; SymbolCreator: a0411947; CompType: IC; U/M: EA

## Sheet TIDA-00204_revE3_PS_1.SchDoc: =DocumentName
size 431 x 279 mm; Date: Not shown in title block; ApprovedBy: Not shown in title block; CheckedBy: Not shown in title block; Author: Not shown in title block; CompanyName: Not shown in title block; DrawnBy: K. Mogensen; Engineer: K. Mogensen; Organization: Not shown in title block; Address1: Not shown in title block; Address2: Not shown in title block; Address3: Not shown in title block; Address4: Not shown in title block; DocumentNumber: 2; Revision: Use project parameter SCH_Rev; SheetNumber: 2; SheetTotal: 10; PageSetup: Record=PageOptions¦CenterHorizontal=True¦CenterVertical=True¦PrintScale=0.62¦XCorrection=1.00¦YCorrection=1.00¦PrintKind=0¦BorderSize=5000000¦LeftOffset=0¦BottomOffset=0¦Orientation=2¦PaperLength=1000¦PaperWidth=1000¦Scale=100¦PaperSource=15¦PrintQuality=600¦MediaType=1¦DitherType=10¦PaperKind=Letter¦PrintScaleMode=1
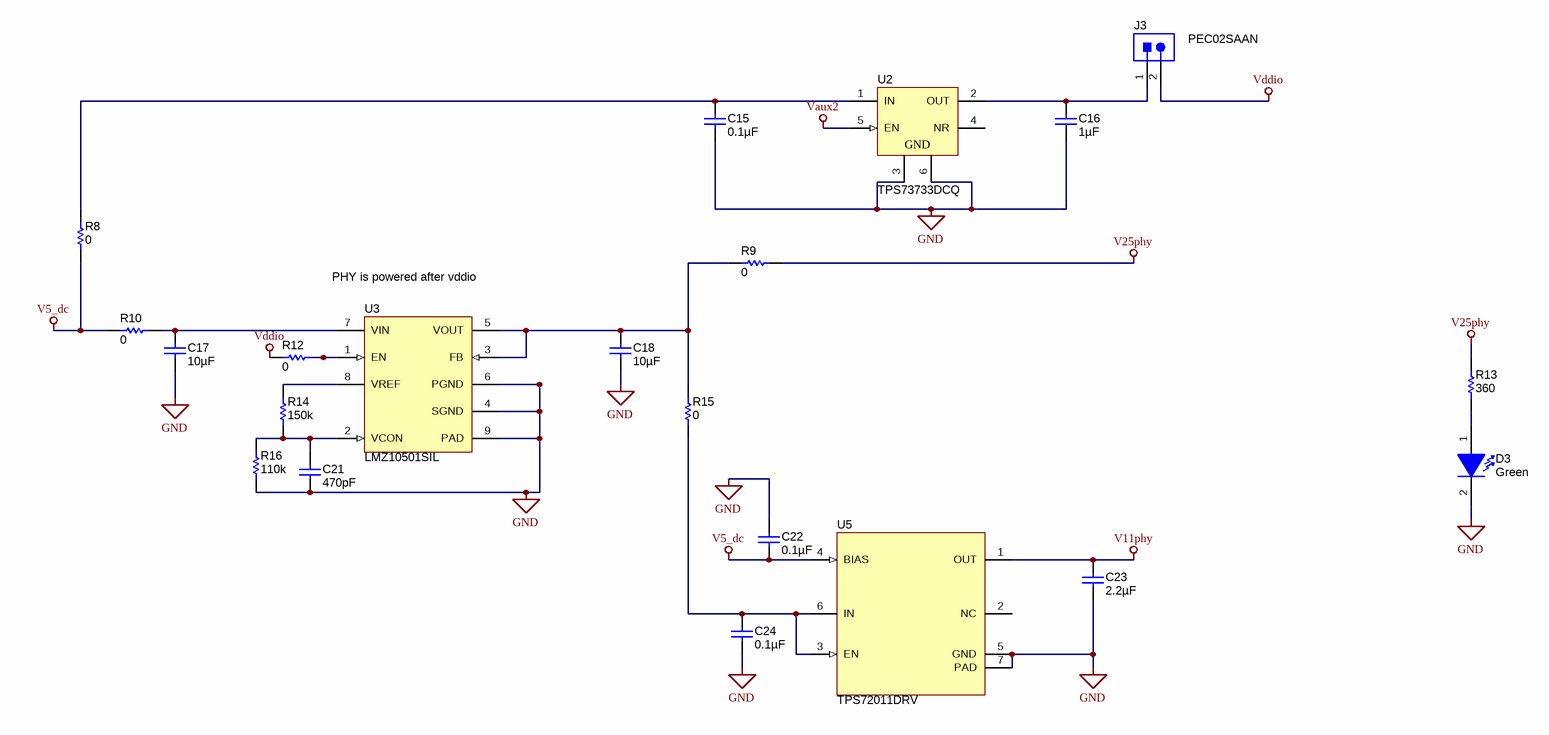
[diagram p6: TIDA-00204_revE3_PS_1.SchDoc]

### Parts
C15  ValueDisplayed: 0.1µF  [0402]  (hidden comment: GRM155R71C104KA88D)
C16  ValueDisplayed: 1µF  [0603]  (hidden comment: GRM188R71A105KA61D)
C17  ValueDisplayed: 10µF  [0603]  (hidden comment: C1608X5R1E106M080AC)
C18  ValueDisplayed: 10µF  [0603]  (hidden comment: C1608X5R1E106M080AC)
C21  ValueDisplayed: 470pF  [0402]  (hidden comment: GRM155R71H471KA01D)
C22  ValueDisplayed: 0.1µF  [0402]  (hidden comment: GRM155R71C104KA88D)
C23  ValueDisplayed: 2.2µF  [0603]  (hidden comment: GRM188R71A225KE15D)
C24  ValueDisplayed: 0.1µF  [0402]  (hidden comment: GRM155R71A104KA01D)
D3  value Green  [LG L29K_GREEN]  (hidden comment: LG L29K-G2J1-24-Z)
J3  PEC02SAAN  [CONN_PEC02SAAN]
R8  ValueDisplayed: 0  [0603]  (hidden comment: CRCW06030000Z0EA)
R9  ValueDisplayed: 0  [0603]  (hidden comment: CRCW06030000Z0EA)
R10  ValueDisplayed: 0  [0603]  (hidden comment: CRCW06030000Z0EA)
R12  ValueDisplayed: 0  [0603]  (hidden comment: CRCW06030000Z0EA)
R13  ValueDisplayed: 360  [0402]  (hidden comment: CRCW0402360RJNED)
R14  ValueDisplayed: 150k  [0402]  (hidden comment: CRCW0402150KFKED)
R15  ValueDisplayed: 0  [0603]  (hidden comment: CRCW06030000Z0EA)
R16  ValueDisplayed: 110k  [0402]  (hidden comment: CRCW0402110KFKED)
U2  TPS73733DCQ  [DCQ0006A_N]
U3  LMZ10501SIL  [SIL0008A]
U5  TPS72011DRV  [DRV0006A]

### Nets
GND: C15.2 C16.2 C17.2 C18.2 C21.2 C22.1 C23.2 C24.1 D3.2(K) R16.1 U2.3(GND) U2.6(GND) U3.4(SGND) U3.6(PGND) U3.9(PAD) U5.5(GND) U5.7(PAD)
V5_dc: C22.2 R8.1 R10.1 U5.4(BIAS)  [project net V5__DC_Sitara]
V11phy: C23.1 U5.1(OUT)
V25phy: R9.2 R13.2
Vaux2: U2.5(EN)
Vddio: J3.2 R12.1
NetC15_1: C15.1 R8.2 U2.1(IN)
NetC16_1: C16.1 J3.1 U2.2(OUT)
NetC17_1: C17.1 R10.2 U3.7(VIN)
NetC18_1: C18.1 R9.1 R15.2 U3.3(FB) U3.5(VOUT)
NetC21_1: C21.1 R14.1 R16.2 U3.2(VCON)
NetC24_2: C24.2 R15.1 U5.3(EN) U5.6(IN)
NetD3_1: D3.1(A) R13.1
NetR12_2: R12.2 U3.1(EN)
NetR14_2: R14.2 U3.8(VREF)

Not connected (* = marked no-connect by the designer): U2 4(NR); U5 2(NC)

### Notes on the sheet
- (near U3) PHY is powered after vddio

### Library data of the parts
C15 C22 = GRM155R71C104KA88D: as C55-C58 on sheet TIDA-00204_revE3_PHY_2
C16 = GRM188R71A105KA61D: CAP, CERM, 1 µF, 10 V, +/- 10%, X7R, 0603; Manufacturer: MuRata; Polarized: N; CompType: Capacitor; Value: 1uF; U/M: EA; Cap_F: 0.000001; Tolerance_%: 10; ESR_ohm: 0.011; Value1: 0.011 ohm; Value2: 10V; TaMin_C: -55; TaMax_C: 125
C17 C18 = C1608X5R1E106M080AC: as C63 on sheet TIDA-00204_revE3_PHY_2
C21 = GRM155R71H471KA01D: CAP, CERM, 470 pF, 50 V, +/- 10%, X7R, 0402; Manufacturer: MuRata; Polarized: N; CompType: Capacitor; Value: 470pF; U/M: EA; Cap_F: 0.00000000047; Tolerance_%: 10; Value1: Unknown; VDC_V: 50; Value2: 50V; TaMin_C: -55; TaMax_C: 125
C23 = GRM188R71A225KE15D: CAP, CERM, 2.2 µF, 10 V, +/- 10%, X7R, 0603; Manufacturer: MuRata; Polarized: N; CompType: Capacitor; Value: 2.2uF; U/M: EA; Cap_F: 0.0000022; Tolerance_%: 10; ESR_ohm: 0.009; Value1: 0.009 ohm; Value2: 10V; TaMin_C: -55; TaMax_C: 125
C24 = GRM155R71A104KA01D: CAP, CERM, 0.1 µF, 10 V, +/- 10%, X7R, 0402; Manufacturer: MuRata; Polarized: N; CompType: Capacitor; Value: 0.1uF; U/M: EA; Cap_F: 0.0000001; Tolerance_%: 10; Value1: Unknown; Value2: 10V; TaMin_C: -55; TaMax_C: 125
D3 = LG L29K-G2J1-24-Z: as D11 on sheet TIDA-00204_revE3_PHY_2
J3 = PEC02SAAN: as J1 on sheet TIDA-00204_revE3_PS_0
R8-R10 R12 R15 = CRCW06030000Z0EA: RES, 0, 5%, 0.1 W, 0603; Manufacturer: Vishay-Dale; CompType: Resistor; Value: 0; Value_Code: 0000; Tolerance_%: 5; Power_W: 0.1; Value2: 0.1W; VDC_V: 75; TempCo: 200 ppm/C; EIA_Code: E24; U/M: EA
R13 = CRCW0402360RJNED: RES, 360, 5%, 0.063 W, 0402; Manufacturer: Vishay-Dale; CompType: Resistor; Value: 360; Value_Code: 360R; Tolerance_%: 5; Power_W: 0.063; Value2: 0.063W; VDC_V: 50; TempCo: 200 ppm/C; EIA_Code: E24; U/M: EA
R14 = CRCW0402150KFKED: RES, 150 k, 1%, 0.063 W, 0402; Manufacturer: Vishay-Dale; CompType: Resistor; Value: 150k; Res_ohm: 150000; Tolerance_%: 1; Power_W: 0.063; Value2: 0.063W; VDC_V: 50; TempCo: 100 ppm/C; EIA_Code: E96; U/M: EA
R16 = CRCW0402110KFKED: RES, 110 k, 1%, 0.063 W, 0402; Manufacturer: Vishay-Dale; CompType: Resistor; Value: 110k; Res_ohm: 110000; Tolerance_%: 1; Power_W: 0.063; Value2: 0.063W; VDC_V: 50; TempCo: 100 ppm/C; EIA_Code: E96; U/M: EA
U2 = TPS73733DCQ: Single Output LDO, 1 A, Fixed 3.3 V Output, 2.2 to 5.5 V Input, with Reverse Current Protection, 6-pin SOT-223 (DCQ), -40 to 125 degC, Green (RoHS & no Sb/Br); Manufacturer: Texas Instruments; Alternate Manufacturer: None; Alternate PartNumber: Equivalent; Accuracy(%): 3; Fixed Output Options(V): 3.3; Iout(Max)(A): 1; Iq(Typ)(mA): 0.3; Rating: Catalog; SubFamily: Single Channel LDO; Vdo(Typ)(mV): 130; Vin(Max)(V): 5.5; Vin(Min)(V): 2.2
U3 = LMZ10501SIL: 1A SIMPLE SWITCHER® Nano Module with 5.5V Maximum Input Voltage, SIL0008A; Alternate Manufacturer: None; Manufacturer: Texas Instruments; SymbolCreator: a0799628; CompType: IC; U/M: EA
U5 = TPS72011DRV: 350mA, Ultra-Low VIN, RF Low-Dropout Linear Regulator with Bias Pin, DRV0006A; Alternate Manufacturer: None; Manufacturer: Texas Instruments; SymbolCreator: Altium; CompType: IC; U/M: EA

## Sheet TIDA-00204_revE3_PS_2.SchDoc: =DocumentName
size 431 x 279 mm; Date: Not shown in title block; ApprovedBy: Not shown in title block; CheckedBy: Not shown in title block; Author: Not shown in title block; CompanyName: Not shown in title block; DrawnBy: K. Mogensen; Engineer: K. Mogensen; Organization: Not shown in title block; Address1: Not shown in title block; Address2: Not shown in title block; Address3: Not shown in title block; Address4: Not shown in title block; DocumentNumber: 5; Revision: Use project parameter SCH_Rev; SheetNumber: 5; SheetTotal: 10; PageSetup: Record=PageOptions¦CenterHorizontal=True¦CenterVertical=True¦PrintScale=0.62¦XCorrection=1.00¦YCorrection=1.00¦PrintKind=0¦BorderSize=5000000¦LeftOffset=0¦BottomOffset=0¦Orientation=2¦PaperLength=1000¦PaperWidth=1000¦Scale=100¦PaperSource=15¦PrintQuality=600¦MediaType=1¦DitherType=10¦PaperKind=Letter¦PrintScaleMode=1
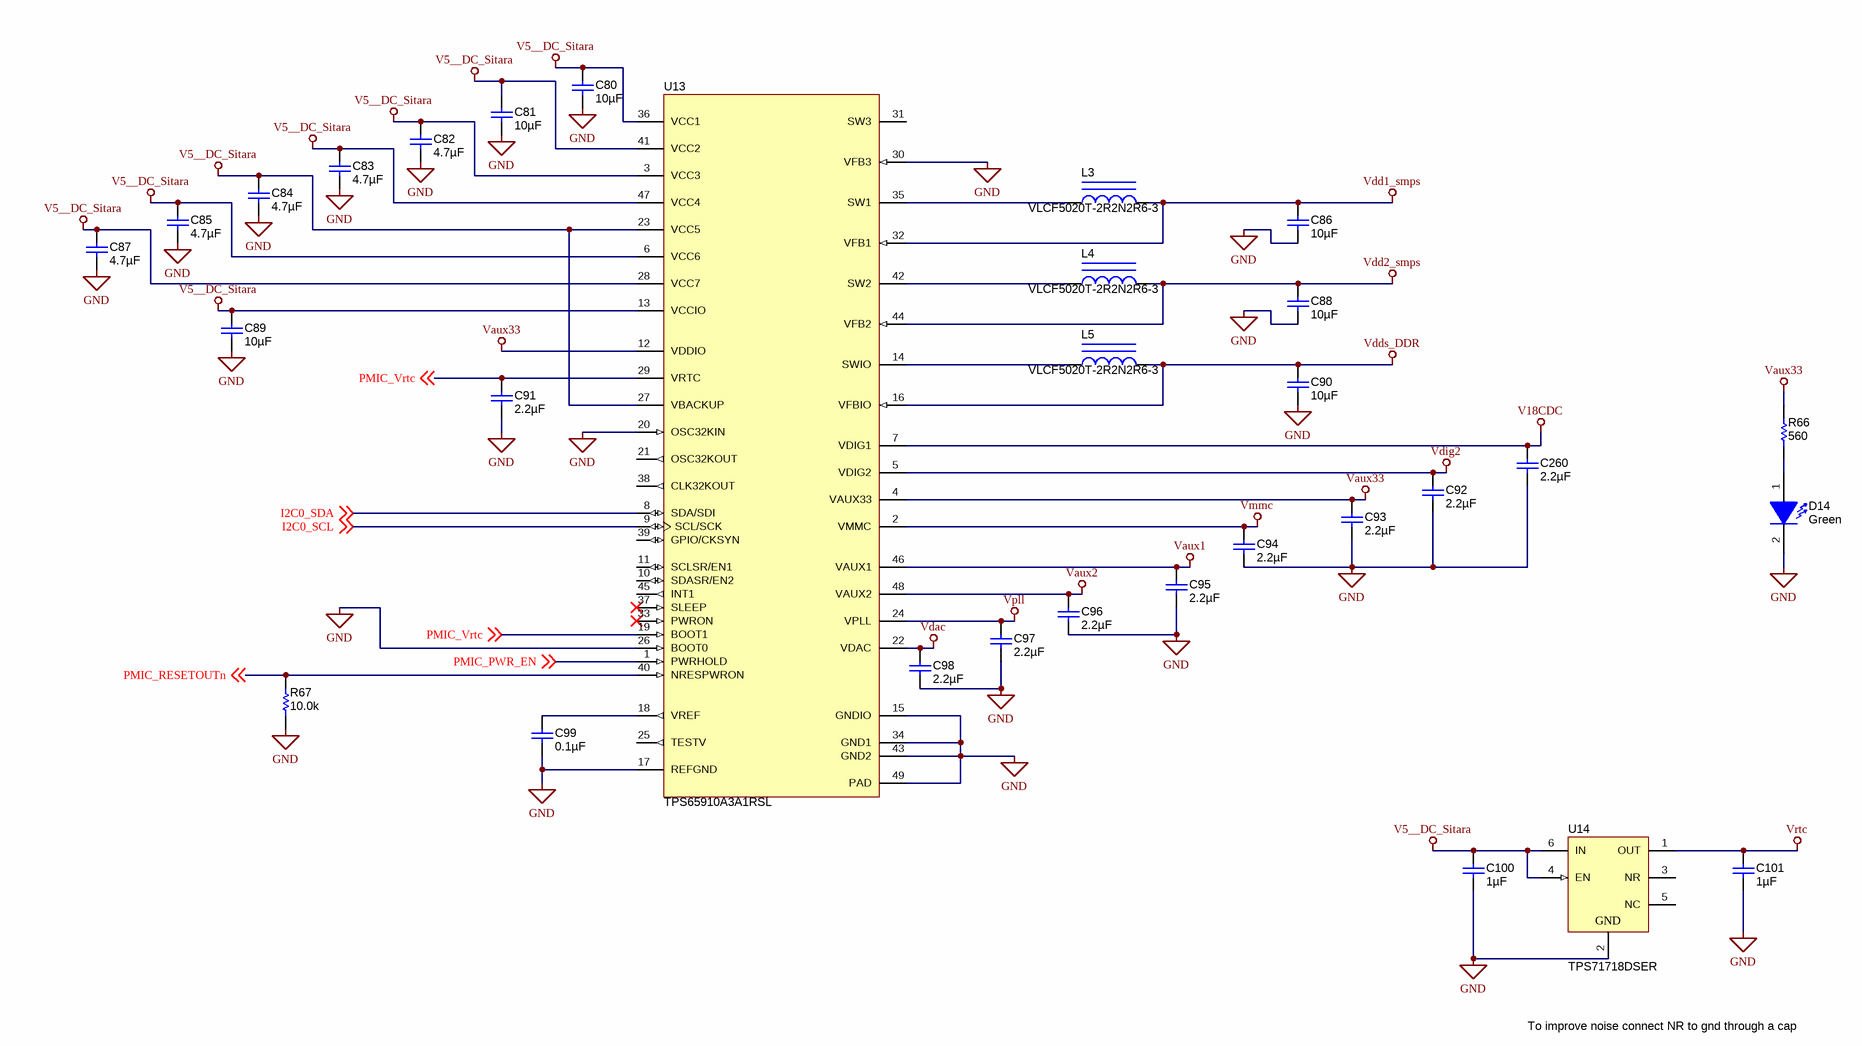
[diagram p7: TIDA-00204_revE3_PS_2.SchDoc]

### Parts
C80  ValueDisplayed: 10µF  [0603]  (hidden comment: C1608X5R1E106M080AC)
C81  ValueDisplayed: 10µF  [0603]  (hidden comment: C1608X5R1E106M080AC)
C82  ValueDisplayed: 4.7µF  [0603]  (hidden comment: GRM188R61C475KAAJ)
C83  ValueDisplayed: 4.7µF  [0603]  (hidden comment: GRM188R61C475KAAJ)
C84  ValueDisplayed: 4.7µF  [0603]  (hidden comment: GRM188R61C475KAAJ)
C85  ValueDisplayed: 4.7µF  [0603]  (hidden comment: GRM188R61C475KAAJ)
C86  ValueDisplayed: 10µF  [0603]  (hidden comment: C1608X5R1E106M080AC)
C87  ValueDisplayed: 4.7µF  [0603]  (hidden comment: GRM188R61C475KAAJ)
C88  ValueDisplayed: 10µF  [0603]  (hidden comment: C1608X5R1E106M080AC)
C89  ValueDisplayed: 10µF  [0603]  (hidden comment: C1608X5R1E106M080AC)
C90  ValueDisplayed: 10µF  [0603]  (hidden comment: C1608X5R1E106M080AC)
C91  ValueDisplayed: 2.2µF  [0603]  (hidden comment: GRM188R71A225KE15D)
C92  ValueDisplayed: 2.2µF  [0603]  (hidden comment: GRM188R71A225KE15D)
C93  ValueDisplayed: 2.2µF  [0603]  (hidden comment: GRM188R71A225KE15D)
C94  ValueDisplayed: 2.2µF  [0603]  (hidden comment: GRM188R71A225KE15D)
C95  ValueDisplayed: 2.2µF  [0603]  (hidden comment: GRM188R71A225KE15D)
C96  ValueDisplayed: 2.2µF  [0603]  (hidden comment: GRM188R71A225KE15D)
C97  ValueDisplayed: 2.2µF  [0603]  (hidden comment: GRM188R71A225KE15D)
C98  ValueDisplayed: 2.2µF  [0603]  (hidden comment: GRM188R71A225KE15D)
C99  ValueDisplayed: 0.1µF  [0402]  (hidden comment: GRM155R71A104KA01D)
C100  ValueDisplayed: 1µF  [0603]  (hidden comment: GRM188R71A105KA61D)
C101  ValueDisplayed: 1µF  [0603]  (hidden comment: GRM188R71A105KA61D)
C260  ValueDisplayed: 2.2µF  [0603]  (hidden comment: GRM188R71A225KE15D)
D14  value Green  [LG L29K_GREEN]  (hidden comment: LG L29K-G2J1-24-Z)
L3  VLCF5020T-2R2N2R6-3  [VLCF5020]
L4  VLCF5020T-2R2N2R6-3  [VLCF5020]
L5  VLCF5020T-2R2N2R6-3  [VLCF5020]
R66  ValueDisplayed: 560  [0402]  (hidden comment: CRCW0402560RJNED)
R67  ValueDisplayed: 10.0k  [0402]  (hidden comment: CRCW040210K0FKED)
U13  TPS65910A3A1RSL  [RSL0048A]
U14  TPS71718DSER  [DSE0006A]

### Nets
GND: C80.2 C81.2 C82.2 C83.2 C84.2 C85.2 C86.2 C87.2 C88.2 C89.2 C90.2 C91.2 C92.2 C93.2 C94.2 C95.2 C96.2 C97.2 C98.2 C99.2 C100.2 C101.2 C260.2 D14.2(K) R67.1 U13.15(GNDIO) U13.17(REFGND) U13.20(OSC32KIN) U13.26(BOOT0) U13.30(VFB3) U13.34(GND1) U13.43(GND2) U13.49(PAD) U14.2(GND)
V5__DC_Sitara: C80.1 C81.1 C82.1 C83.1 C84.1 C85.1 C87.1 C89.1 C100.1 U13.3(VCC3) U13.6(VCC6) U13.13(VCCIO) U13.23(VCC5) U13.27(VBACKUP) U13.28(VCC7) U13.36(VCC1) U13.41(VCC2) U13.47(VCC4) U14.4(EN) U14.6(IN)
V18CDC: C260.1 U13.7(VDIG1)
Vaux1: C95.1 U13.46(VAUX1)
Vaux2: C96.1 U13.48(VAUX2)
Vaux33: C93.1 R66.2 U13.4(VAUX33) U13.12(VDDIO)
Vdac: C98.1 U13.22(VDAC)
Vdd1_smps: C86.1 L3.2 U13.32(VFB1)
Vdd2_smps: C88.1 L4.2 U13.44(VFB2)
Vdds_DDR: C90.1 L5.2 U13.16(VFBIO)
Vdig2: C92.1 U13.5(VDIG2)
Vmmc: C94.1 U13.2(VMMC)
Vpll: C97.1 U13.24(VPLL)
Vrtc: C101.1 U14.1(OUT)
I2C0_SCL: U13.9(SCL/SCK) ; off-sheet I2C0_SCL
I2C0_SDA: U13.8(SDA/SDI) ; off-sheet I2C0_SDA
PMIC_PWR_EN: U13.1(PWRHOLD) ; off-sheet PMIC_PWR_EN
PMIC_RESETOUTn: R67.2 U13.40(NRESPWRON) ; off-sheet PMIC_RESETOUTn
PMIC_Vrtc: C91.1 U13.19(BOOT1) U13.29(VRTC) ; off-sheet PMIC_Vrtc
NetC99_1: C99.1 U13.18(VREF)
NetD14_1: D14.1(A) R66.1
NetL3_1: L3.1 U13.35(SW1)
NetL4_1: L4.1 U13.42(SW2)
NetL5_1: L5.1 U13.14(SWIO)

Not connected (* = marked no-connect by the designer): U13 10(SDASR/EN2) 11(SCLSR/EN1) 21(OSC32KOUT) 25(TESTV) 31(SW3) 33(PWRON)* 37(SLEEP)* 38(CLK32KOUT) 39(GPIO/CKSYN) 45(INT1); U14 3(NR) 5(NC)

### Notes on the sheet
- To improve noise connect NR to gnd through a cap

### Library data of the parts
C80 C81 C86 C88-C90 = C1608X5R1E106M080AC: as C63 on sheet TIDA-00204_revE3_PHY_2
C82-C85 C87 = GRM188R61C475KAAJ: as C13 on sheet TIDA-00204_revE3_PS_0
C91-C98 C260 = GRM188R71A225KE15D: as C23 on sheet TIDA-00204_revE3_PS_1
C99 = GRM155R71a104ka01D: CAP, CERM, 0.1 µF, 10 V, +/- 10%, X7R, 0402; Manufacturer: MuRata; Polarized: N; CompType: Capacitor; Value: 0.1uF; U/M: EA; Cap_F: 0.0000001; Tolerance_%: 10; Value1: Unknown; Value2: 10V; TaMin_C: -55; TaMax_C: 125
C100 C101 = GRM188R71A105KA61D: as C16 on sheet TIDA-00204_revE3_PS_1
D14 = LG L29K-G2J1-24-Z: as D11 on sheet TIDA-00204_revE3_PHY_2
L3-L5 = VLCF5020T-2R2N2R6-3: Inductor, Shielded, Ferrite, 2.2 µH, 2.62 A, 0.043 ohm, SMD; Manufacturer: TDK; Value: 2.2uH; Ind_H: 2.2E-6; ValueDisplayed: 2.2µH; Imax_A: 2.62; Irms: 3.25A @ 40C rise; Isat: 2.62A @ 30% inductance drop; DCR_ohm: 0.043; Value2: 2.62A
R66 = CRCW0402560RJNED: as R52-R54 on sheet TIDA-00204_revE3_PHY_2
R67 = CRCW040210K0FKED: as R41 on sheet TIDA-00204_revE3_PHY_2
U13 = TPS65910A3A1RSL: Integrated Power-Management Unit Top Specification, RSL0048A; Alternate Manufacturer: None; Manufacturer: Texas Instruments; SymbolCreator: Altium; CompType: IC; U/M: EA
U14 = TPS71718DSER: Single Output High PSRR LDO, 150 mA, Fixed 1.8 V Output, 2.5 to 6.5 V Input, with Low IQ, 6-pin WSON (DSE), -40 to 125 degC, Green (RoHS & no Sb/Br); Manufacturer: Texas Instruments; Alternate Manufacturer: None; Alternate PartNumber: Equivalent; Accuracy(%): 3; Fixed Output Options(V): 1.8; Iout(Max)(A): 0.15; Iq(Typ)(mA): 0.05; SubFamily: Single Channel LDO; Vdo(Typ)(mV): 170; Vin(Max)(V): 6.5; Vin(Min)(V): 2.5

## Sheet TIDA-00204_revE3_Sitara_PS.SchDoc: =DocumentName
size 431 x 279 mm; Date: Not shown in title block; ApprovedBy: Not shown in title block; CheckedBy: Not shown in title block; Author: Not shown in title block; CompanyName: Not shown in title block; DrawnBy: K. Mogensen; Engineer: K. Mogensen; Organization: Not shown in title block; Address1: Not shown in title block; Address2: Not shown in title block; Address3: Not shown in title block; Address4: Not shown in title block; DocumentNumber: 6; Revision: Use project parameter SCH_Rev; SheetNumber: 6; SheetTotal: 10; PageSetup: Record=PageOptions¦CenterHorizontal=True¦CenterVertical=True¦PrintScale=0.62¦XCorrection=1.00¦YCorrection=1.00¦PrintKind=0¦BorderSize=5000000¦LeftOffset=0¦BottomOffset=0¦Orientation=2¦PaperLength=1000¦PaperWidth=1000¦Scale=100¦PaperSource=15¦PrintQuality=600¦MediaType=1¦DitherType=10¦PaperKind=Letter¦PrintScaleMode=1
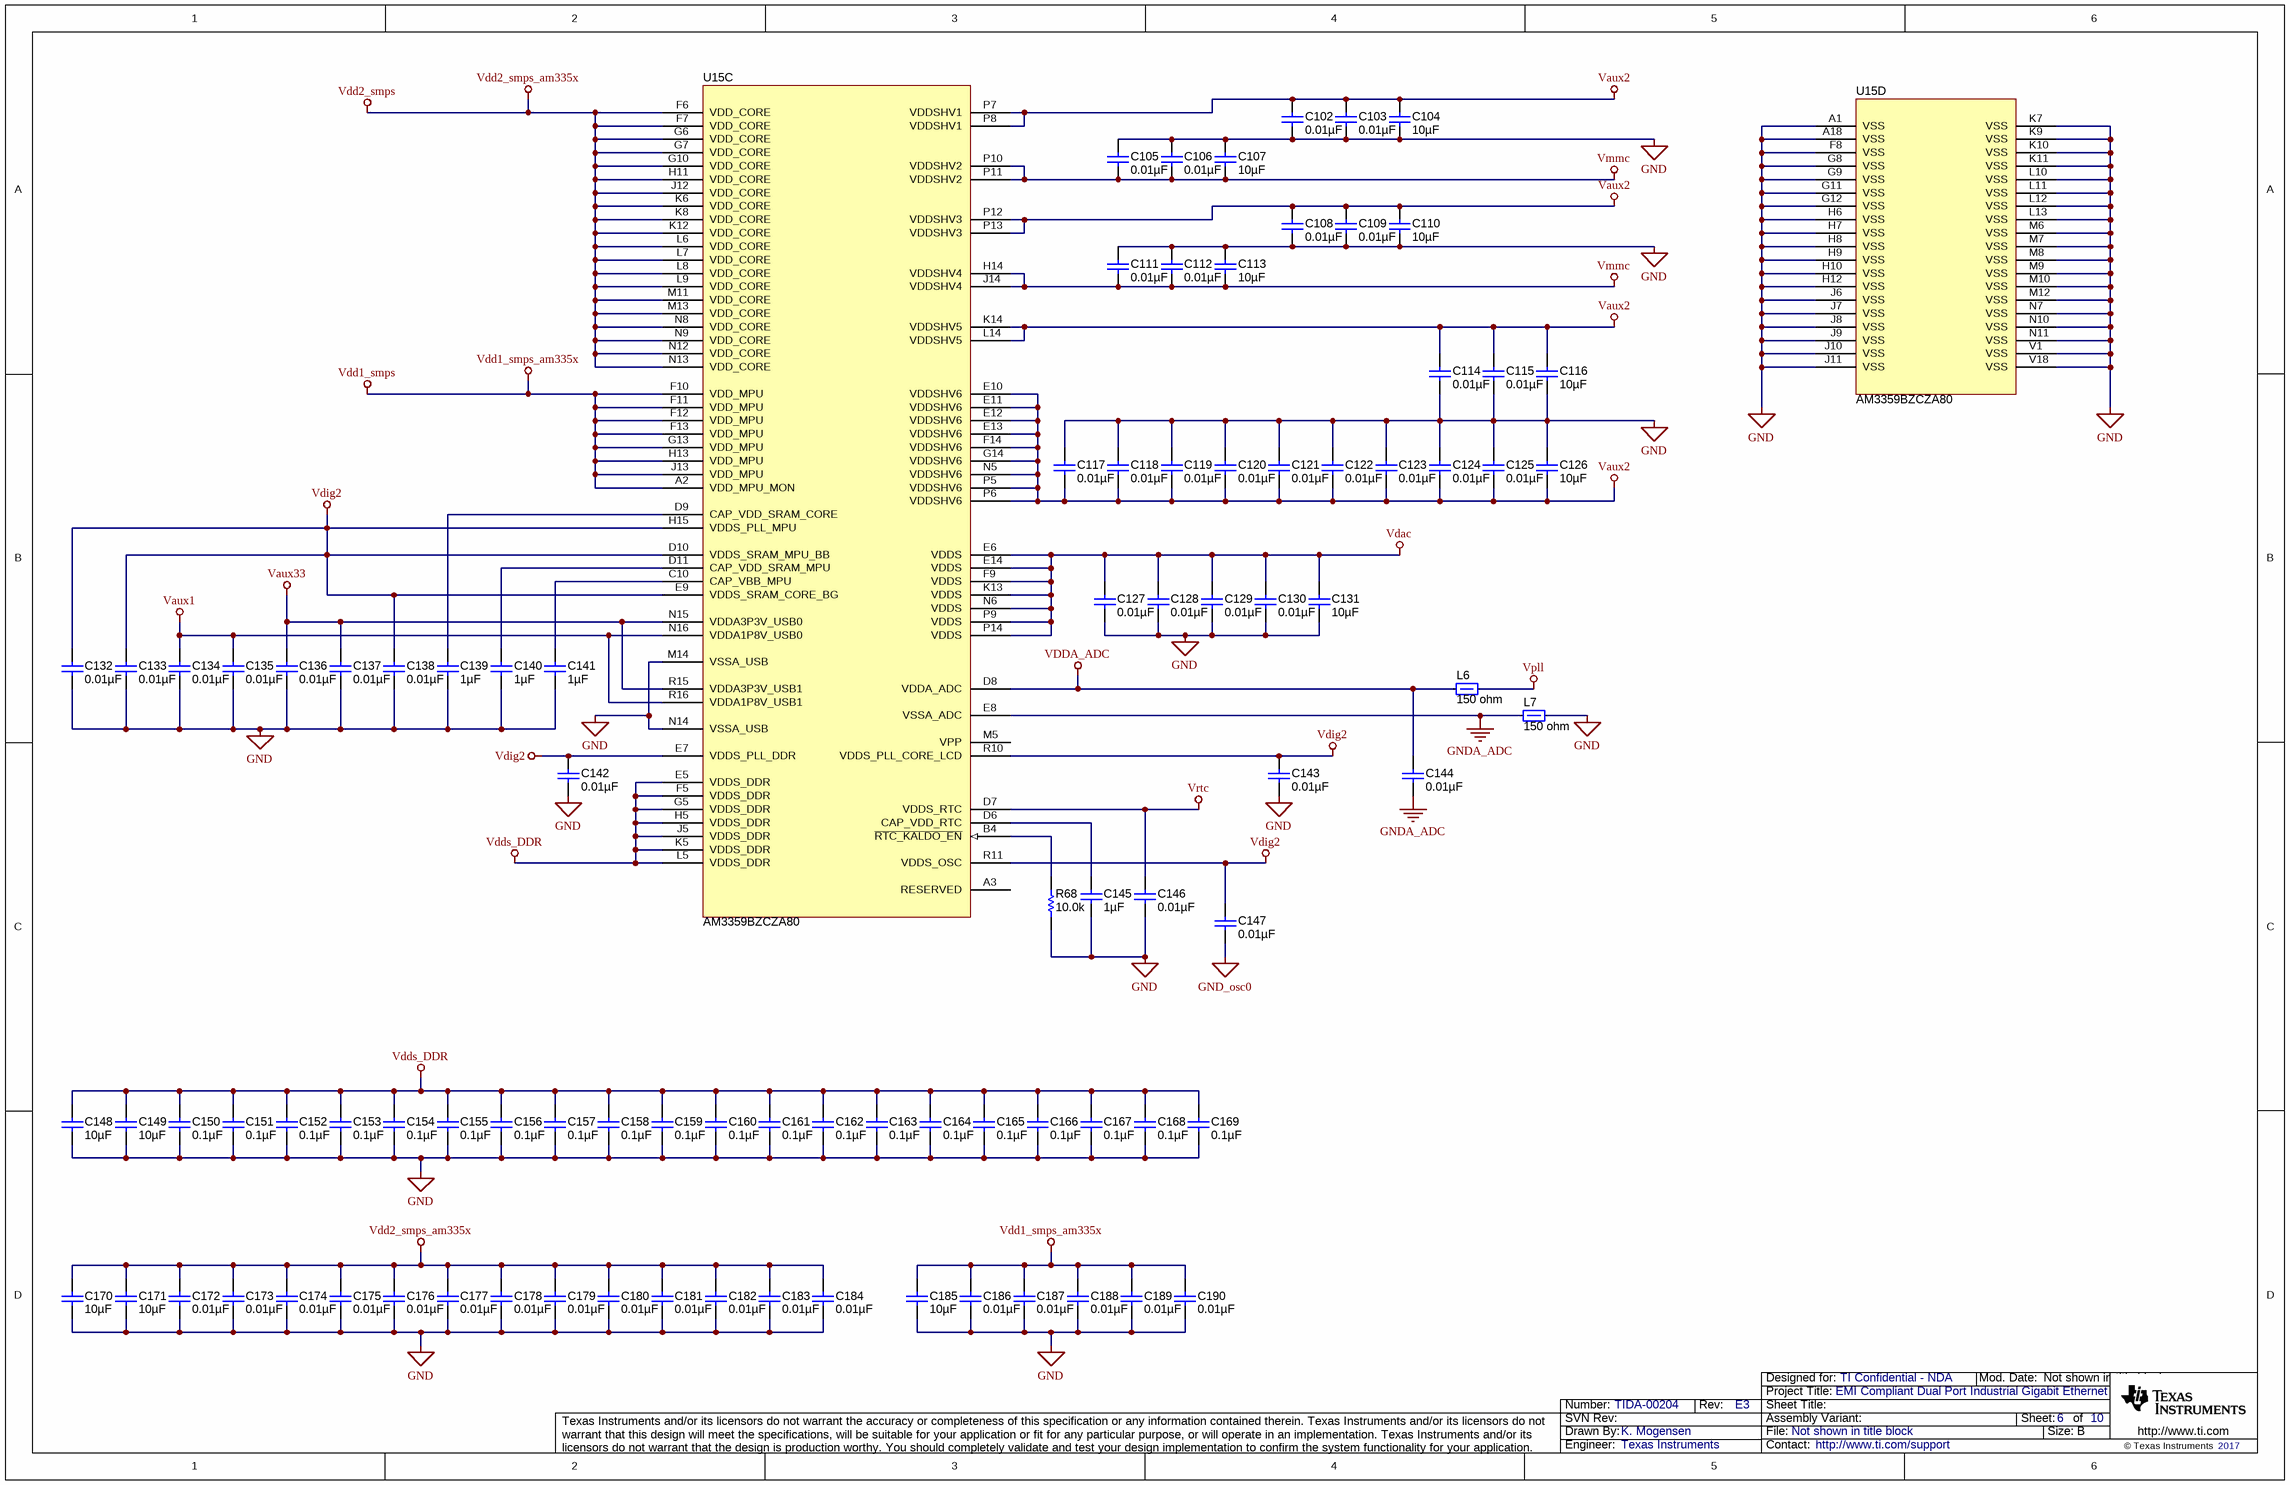
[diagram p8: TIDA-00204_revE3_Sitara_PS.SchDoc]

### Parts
C102  ValueDisplayed: 0.01µF  [0201]  (hidden comment: GRM033R71A103KA01D)
C103  ValueDisplayed: 0.01µF  [0201]  (hidden comment: GRM033R71A103KA01D)
C104  ValueDisplayed: 10µF  [0603]  (hidden comment: C1608X5R1E106M080AC)
C105  ValueDisplayed: 0.01µF  [0201]  (hidden comment: GRM033R71A103KA01D)
C106  ValueDisplayed: 0.01µF  [0201]  (hidden comment: GRM033R71A103KA01D)
C107  ValueDisplayed: 10µF  [0603]  (hidden comment: C1608X5R1E106M080AC)
C108  ValueDisplayed: 0.01µF  [0201]  (hidden comment: GRM033R71A103KA01D)
C109  ValueDisplayed: 0.01µF  [0201]  (hidden comment: GRM033R71A103KA01D)
C110  ValueDisplayed: 10µF  [0603]  (hidden comment: C1608X5R1E106M080AC)
C111  ValueDisplayed: 0.01µF  [0201]  (hidden comment: GRM033R71A103KA01D)
C112  ValueDisplayed: 0.01µF  [0201]  (hidden comment: GRM033R71A103KA01D)
C113  ValueDisplayed: 10µF  [0603]  (hidden comment: C1608X5R1E106M080AC)
C114  ValueDisplayed: 0.01µF  [0201]  (hidden comment: GRM033R71A103KA01D)
C115  ValueDisplayed: 0.01µF  [0201]  (hidden comment: GRM033R71A103KA01D)
C116  ValueDisplayed: 10µF  [0603]  (hidden comment: C1608X5R1E106M080AC)
C117  ValueDisplayed: 0.01µF  [0201]  (hidden comment: GRM033R71A103KA01D)
C118  ValueDisplayed: 0.01µF  [0201]  (hidden comment: GRM033R71A103KA01D)
C119  ValueDisplayed: 0.01µF  [0201]  (hidden comment: GRM033R71A103KA01D)
C120  ValueDisplayed: 0.01µF  [0201]  (hidden comment: GRM033R71A103KA01D)
C121  ValueDisplayed: 0.01µF  [0201]  (hidden comment: GRM033R71A103KA01D)
C122  ValueDisplayed: 0.01µF  [0201]  (hidden comment: GRM033R71A103KA01D)
C123  ValueDisplayed: 0.01µF  [0201]  (hidden comment: GRM033R71A103KA01D)
C124  ValueDisplayed: 0.01µF  [0201]  (hidden comment: GRM033R71A103KA01D)
C125  ValueDisplayed: 0.01µF  [0201]  (hidden comment: GRM033R71A103KA01D)
C126  ValueDisplayed: 10µF  [0603]  (hidden comment: C1608X5R1E106M080AC)
C127  ValueDisplayed: 0.01µF  [0201]  (hidden comment: GRM033R71A103KA01D)
C128  ValueDisplayed: 0.01µF  [0201]  (hidden comment: GRM033R71A103KA01D)
C129  ValueDisplayed: 0.01µF  [0201]  (hidden comment: GRM033R71A103KA01D)
C130  ValueDisplayed: 0.01µF  [0201]  (hidden comment: GRM033R71A103KA01D)
C131  ValueDisplayed: 10µF  [0603]  (hidden comment: C1608X5R1E106M080AC)
C132  ValueDisplayed: 0.01µF  [0201]  (hidden comment: GRM033R71A103KA01D)
C133  ValueDisplayed: 0.01µF  [0201]  (hidden comment: GRM033R71A103KA01D)
C134  ValueDisplayed: 0.01µF  [0201]  (hidden comment: GRM033R71A103KA01D)
C135  ValueDisplayed: 0.01µF  [0201]  (hidden comment: GRM033R71A103KA01D)
C136  ValueDisplayed: 0.01µF  [0201]  (hidden comment: GRM033R71A103KA01D)
C137  ValueDisplayed: 0.01µF  [0201]  (hidden comment: GRM033R71A103KA01D)
C138  ValueDisplayed: 0.01µF  [0201]  (hidden comment: GRM033R71A103KA01D)
C139  ValueDisplayed: 1µF  [0201]  (hidden comment: CL03A105MP3NSNC)
C140  ValueDisplayed: 1µF  [0201]  (hidden comment: CL03A105MP3NSNC)
C141  ValueDisplayed: 1µF  [0201]  (hidden comment: CL03A105MP3NSNC)
C142  ValueDisplayed: 0.01µF  [0201]  (hidden comment: GRM033R71A103KA01D)
C143  ValueDisplayed: 0.01µF  [0201]  (hidden comment: GRM033R71A103KA01D)
C144  ValueDisplayed: 0.01µF  [0201]  (hidden comment: GRM033R71A103KA01D)
C145  ValueDisplayed: 1µF  [0201]  (hidden comment: CL03A105MP3NSNC)
C146  ValueDisplayed: 0.01µF  [0201]  (hidden comment: GRM033R71A103KA01D)
C147  ValueDisplayed: 0.01µF  [0201]  (hidden comment: GRM033R71A103KA01D)
C148  ValueDisplayed: 10µF  [0603]  (hidden comment: C1608X5R1E106M080AC)
C149  ValueDisplayed: 10µF  [0603]  (hidden comment: C1608X5R1E106M080AC)
C150  ValueDisplayed: 0.1µF  [0201]  (hidden comment: CL03A104KP3NNNC)
C151  ValueDisplayed: 0.1µF  [0201]  (hidden comment: CL03A104KP3NNNC)
C152  ValueDisplayed: 0.1µF  [0201]  (hidden comment: CL03A104KP3NNNC)
C153  ValueDisplayed: 0.1µF  [0201]  (hidden comment: CL03A104KP3NNNC)
C154  ValueDisplayed: 0.1µF  [0201]  (hidden comment: CL03A104KP3NNNC)
C155  ValueDisplayed: 0.1µF  [0201]  (hidden comment: CL03A104KP3NNNC)
C156  ValueDisplayed: 0.1µF  [0201]  (hidden comment: CL03A104KP3NNNC)
C157  ValueDisplayed: 0.1µF  [0201]  (hidden comment: CL03A104KP3NNNC)
C158  ValueDisplayed: 0.1µF  [0201]  (hidden comment: CL03A104KP3NNNC)
C159  ValueDisplayed: 0.1µF  [0201]  (hidden comment: CL03A104KP3NNNC)
C160  ValueDisplayed: 0.1µF  [0201]  (hidden comment: CL03A104KP3NNNC)
C161  ValueDisplayed: 0.1µF  [0201]  (hidden comment: CL03A104KP3NNNC)
C162  ValueDisplayed: 0.1µF  [0201]  (hidden comment: CL03A104KP3NNNC)
C163  ValueDisplayed: 0.1µF  [0201]  (hidden comment: CL03A104KP3NNNC)
C164  ValueDisplayed: 0.1µF  [0201]  (hidden comment: CL03A104KP3NNNC)
C165  ValueDisplayed: 0.1µF  [0201]  (hidden comment: CL03A104KP3NNNC)
C166  ValueDisplayed: 0.1µF  [0201]  (hidden comment: CL03A104KP3NNNC)
C167  ValueDisplayed: 0.1µF  [0201]  (hidden comment: CL03A104KP3NNNC)
C168  ValueDisplayed: 0.1µF  [0201]  (hidden comment: CL03A104KP3NNNC)
C169  ValueDisplayed: 0.1µF  [0201]  (hidden comment: CL03A104KP3NNNC)
C170  ValueDisplayed: 10µF  [0603]  (hidden comment: C1608X5R1E106M080AC)
C171  ValueDisplayed: 10µF  [0603]  (hidden comment: C1608X5R1E106M080AC)
C172  ValueDisplayed: 0.01µF  [0201]  (hidden comment: GRM033R71A103KA01D)
C173  ValueDisplayed: 0.01µF  [0201]  (hidden comment: GRM033R71A103KA01D)
C174  ValueDisplayed: 0.01µF  [0201]  (hidden comment: GRM033R71A103KA01D)
C175  ValueDisplayed: 0.01µF  [0201]  (hidden comment: GRM033R71A103KA01D)
C176  ValueDisplayed: 0.01µF  [0201]  (hidden comment: GRM033R71A103KA01D)
C177  ValueDisplayed: 0.01µF  [0201]  (hidden comment: GRM033R71A103KA01D)
C178  ValueDisplayed: 0.01µF  [0201]  (hidden comment: GRM033R71A103KA01D)
C179  ValueDisplayed: 0.01µF  [0201]  (hidden comment: GRM033R71A103KA01D)
C180  ValueDisplayed: 0.01µF  [0201]  (hidden comment: GRM033R71A103KA01D)
C181  ValueDisplayed: 0.01µF  [0201]  (hidden comment: GRM033R71A103KA01D)
C182  ValueDisplayed: 0.01µF  [0201]  (hidden comment: GRM033R71A103KA01D)
C183  ValueDisplayed: 0.01µF  [0201]  (hidden comment: GRM033R71A103KA01D)
C184  ValueDisplayed: 0.01µF  [0201]  (hidden comment: GRM033R71A103KA01D)
C185  ValueDisplayed: 10µF  [0603]  (hidden comment: C1608X5R1E106M080AC)
C186  ValueDisplayed: 0.01µF  [0201]  (hidden comment: GRM033R71A103KA01D)
C187  ValueDisplayed: 0.01µF  [0201]  (hidden comment: GRM033R71A103KA01D)
C188  ValueDisplayed: 0.01µF  [0201]  (hidden comment: GRM033R71A103KA01D)
C189  ValueDisplayed: 0.01µF  [0201]  (hidden comment: GRM033R71A103KA01D)
C190  ValueDisplayed: 0.01µF  [0201]  (hidden comment: GRM033R71A103KA01D)
L6  value 150 ohm  [0805_HV]  (hidden comment: LI0805H151R-10)
L7  value 150 ohm  [0805_HV]  (hidden comment: LI0805H151R-10)
R68  ValueDisplayed: 10.0k  [0402]  (hidden comment: CRCW040210K0FKED)
U15  AM3359BZCZA80  [ZCZ0324A]  (parts C,D of 4)

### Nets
GND: C102.2 C103.2 C104.2 C105.1 C106.1 C107.1 C108.2 C109.2 C110.2 C111.1 C112.1 C113.1 C114.2 C115.2 C116.2 C117.1 C118.1 C119.1 C120.1 C121.1 C122.1 C123.1 C124.1 C125.1 C126.1 C127.2 C128.2 C129.2 C130.2 C131.2 C132.2 C133.2 C134.2 C135.2 C136.2 C137.2 C138.2 C139.2 C140.2 C141.2 C142.2 C143.2 C145.2 C146.2 C148.2 C149.2 C150.2 C151.2 C152.2 C153.2 C154.2 C155.2 C156.2 C157.2 C158.2 C159.2 C160.2 C161.2 C162.2 C163.2 C164.2 C165.2 C166.2 C167.2 C168.2 C169.2 C170.2 C171.2 C172.2 C173.2 C174.2 C175.2 C176.2 C177.2 C178.2 C179.2 C180.2 C181.2 C182.2 C183.2 C184.2 C185.2 C186.2 C187.2 C188.2 C189.2 C190.2 L7.2 R68.1 U15.A1(VSS) U15.A18(VSS) U15.F8(VSS) U15.G8(VSS) U15.G9(VSS) U15.G11(VSS) U15.G12(VSS) U15.H6(VSS) U15.H7(VSS) U15.H8(VSS) U15.H9(VSS) U15.H10(VSS) U15.H12(VSS) U15.J6(VSS) U15.J7(VSS) U15.J8(VSS) U15.J9(VSS) U15.J10(VSS) U15.J11(VSS) U15.K7(VSS) U15.K9(VSS) U15.K10(VSS) U15.K11(VSS) U15.L10(VSS) U15.L11(VSS) U15.L12(VSS) U15.L13(VSS) U15.M6(VSS) U15.M7(VSS) U15.M8(VSS) U15.M9(VSS) U15.M10(VSS) U15.M12(VSS) U15.M14(VSSA_USB) U15.N7(VSS) U15.N10(VSS) U15.N11(VSS) U15.N14(VSSA_USB) U15.V1(VSS) U15.V18(VSS)
GND_osc0: C147.2
GNDA_ADC: C144.2 L7.1 U15.E8(VSSA_ADC)
Vaux1: C134.1 C135.1 U15.N16(VDDA1P8V_USB0) U15.R16(VDDA1P8V_USB1)
Vaux2: C102.1 C103.1 C104.1 C108.1 C109.1 C110.1 C114.1 C115.1 C116.1 C117.2 C118.2 C119.2 C120.2 C121.2 C122.2 C123.2 C124.2 C125.2 C126.2 U15.E10(VDDSHV6) U15.E11(VDDSHV6) U15.E12(VDDSHV6) U15.E13(VDDSHV6) U15.F14(VDDSHV6) U15.G14(VDDSHV6) U15.K14(VDDSHV5) U15.L14(VDDSHV5) U15.N5(VDDSHV6) U15.P5(VDDSHV6) U15.P6(VDDSHV6) U15.P7(VDDSHV1) U15.P8(VDDSHV1) U15.P12(VDDSHV3) U15.P13(VDDSHV3)
Vaux33: C136.1 C137.1 U15.N15(VDDA3P3V_USB0) U15.R15(VDDA3P3V_USB1)
Vdac: C127.1 C128.1 C129.1 C130.1 C131.1 U15.E6(VDDS) U15.E14(VDDS) U15.F9(VDDS) U15.K13(VDDS) U15.N6(VDDS) U15.P9(VDDS) U15.P14(VDDS)
Vdd1_smps: C185.1 C186.1 C187.1 C188.1 C189.1 C190.1 U15.A2(VDD_MPU_MON) U15.F10(VDD_MPU) U15.F11(VDD_MPU) U15.F12(VDD_MPU) U15.F13(VDD_MPU) U15.G13(VDD_MPU) U15.H13(VDD_MPU) U15.J13(VDD_MPU)  [also labelled Vdd1_smps_am335x]
Vdd2_smps: C170.1 C171.1 C172.1 C173.1 C174.1 C175.1 C176.1 C177.1 C178.1 C179.1 C180.1 C181.1 C182.1 C183.1 C184.1 U15.F6(VDD_CORE) U15.F7(VDD_CORE) U15.G6(VDD_CORE) U15.G7(VDD_CORE) U15.G10(VDD_CORE) U15.H11(VDD_CORE) U15.J12(VDD_CORE) U15.K6(VDD_CORE) U15.K8(VDD_CORE) U15.K12(VDD_CORE) U15.L6(VDD_CORE) U15.L7(VDD_CORE) U15.L8(VDD_CORE) U15.L9(VDD_CORE) U15.M11(VDD_CORE) U15.M13(VDD_CORE) U15.N8(VDD_CORE) U15.N9(VDD_CORE) U15.N12(VDD_CORE) U15.N13(VDD_CORE)  [also labelled Vdd2_smps_am335x]
VDDA_ADC: C144.1 L6.1 U15.D8(VDDA_ADC)
Vdds_DDR: C148.1 C149.1 C150.1 C151.1 C152.1 C153.1 C154.1 C155.1 C156.1 C157.1 C158.1 C159.1 C160.1 C161.1 C162.1 C163.1 C164.1 C165.1 C166.1 C167.1 C168.1 C169.1 U15.E5(VDDS_DDR) U15.F5(VDDS_DDR) U15.G5(VDDS_DDR) U15.H5(VDDS_DDR) U15.J5(VDDS_DDR) U15.K5(VDDS_DDR) U15.L5(VDDS_DDR)
Vdig2: C132.1 C133.1 C138.1 C142.1 C143.1 C147.1 U15.D10(VDDS_SRAM_MPU_BB) U15.E7(VDDS_PLL_DDR) U15.E9(VDDS_SRAM_CORE_BG) U15.H15(VDDS_PLL_MPU) U15.R10(VDDS_PLL_CORE_LCD) U15.R11(VDDS_OSC)
Vmmc: C105.2 C106.2 C107.2 C111.2 C112.2 C113.2 U15.H14(VDDSHV4) U15.J14(VDDSHV4) U15.P10(VDDSHV2) U15.P11(VDDSHV2)
Vpll: L6.2
Vrtc: C146.1 U15.D7(VDDS_RTC)
NetC139_1: C139.1 U15.D9(CAP_VDD_SRAM_CORE)
NetC140_1: C140.1 U15.D11(CAP_VDD_SRAM_MPU)
NetC141_1: C141.1 U15.C10(CAP_VBB_MPU)
NetC145_1: C145.1 U15.D6(CAP_VDD_RTC)
NetR68_2: R68.2 U15.B4(~{RTC_KALDO_EN})

Not connected (* = marked no-connect by the designer): U15 A3(RESERVED) M5(VPP)

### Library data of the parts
C102 C103 C105 C106 C108 C109 C111 C112 C114 C115 C117-C125 C127-C130 C132-C138 C142-C144 C146 C147 C172-C184 C186-C190 = GRM033R71A103KA01D: as C64 on sheet TIDA-00204_revE3_PHY_2
C104 C107 C110 C113 C116 C126 C131 C148 C149 C170 C171 C185 = C1608X5R1E106M080AC: as C63 on sheet TIDA-00204_revE3_PHY_2
C139-C141 C145 = CL03A105MP3NSNC: CAP, CERM, 1 µF, 10 V, +/- 20%, X5R, 0201; Manufacturer: Samsung; Polarized: N; CompType: Capacitor; Value: 1uF; U/M: EA; Cap_F: 0.000001; Tolerance_%: 20; Value1: Unknown; VDC_V: 10; Value2: 10V; TaMin_C: -55; TaMax_C: 85
C150-C169 = CL03A104KP3NNNC: as C252 on sheet TIDA-00204_revE3_PHY_2
L6 L7 = LI0805H151R-10: Ferrite Bead, 150 ohm @ 100 MHz, 0.8 A, 0805; Manufacturer: Laird-Signal Integrity Products; Imax_A: 0.8; DCR_ohm: 0.15; Value1: 0.15 ohm; Value2: 0.8A; ZTyp@100MHz_Ohm: 150
R68 = CRCW040210K0FKED: as R41 on sheet TIDA-00204_revE3_PHY_2
U15 = AM3359BZCZA80: Sitara Processors, ZCZ0324A; Alternate Manufacturer: None; Manufacturer: Texas Instruments; SymbolCreator: Altium; CompType: IC; U/M: EA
